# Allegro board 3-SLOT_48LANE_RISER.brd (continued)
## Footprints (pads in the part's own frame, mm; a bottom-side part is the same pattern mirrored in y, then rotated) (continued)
C0201
  rect 0.279x0.33 smd: 1(-0.229,0) 2(0.229,0)
C0201#2
  rect 0.305x0.381 smd: 1(-0.267,0) 2(0.267,0)
C0402
  rect 0.457x0.508 smd: 1(-0.4,0) 2(0.4,0)
C0603
  rect 0.813x0.711 smd: 1(-0.737,0) 2(0.737,0)
C0805
  rect 1.118x1.372 smd: 1(-0.95,0) 2(0.95,0)
C1206
  rect 1.168x1.575 smd: 1(-1.473,0) 2(1.473,0)
DELTAL_COUPON_7P
  round 0.66 smd: 1(-0.504,1.301) 2(0.497,1.301)
  round 1.143 hole 1.041: 3(-1.274,-2.498) 4(1.266,-2.498) 5(-1.274,3.852) 6(1.266,3.852)
  custom 0.743x0.743 smd: 7(-0.009,-0.37)
  round 0.508 hole 0.406: 8(-1.27,0.457) 9(-1.27,-0.762) 10(-0.025,-0.762) 11(1.27,-0.762) 12(1.27,0.457)
GF_PCIE_X16
  rect 0.762x3.2 smd: A1(-11.5,-3.42) B81(70.5,-3.42)
  rect 0.762x4.216 smd: A2(-10.5,-3.92) A3(-9.5,-3.92) A4(-8.5,-3.92) A5(-7.5,-3.92) A6(-6.5,-3.92) A7(-5.5,-3.92) A8(-4.5,-3.92) A9(-3.5,-3.92) A10(-2.5,-3.92) A11(-1.5,-3.92) A12(1.5,-3.92) A13(2.5,-3.92) A14(3.5,-3.92) A15(4.5,-3.92) A16(5.5,-3.92) A17(6.5,-3.92) A18(7.5,-3.92) A19(8.5,-3.92) A20(9.5,-3.92) A21(10.5,-3.92) A22(11.5,-3.92) A23(12.5,-3.92) A24(13.5,-3.92) A25(14.5,-3.92) A26(15.5,-3.92) A27(16.5,-3.92) A28(17.5,-3.92) A29(18.5,-3.92) A30(19.5,-3.92) A31(20.5,-3.92) A32(21.5,-3.92) A33(22.5,-3.92) A34(23.5,-3.92) A35(24.5,-3.92) A36(25.5,-3.92) A37(26.5,-3.92) A38(27.5,-3.92) A39(28.5,-3.92) A40(29.5,-3.92) A41(30.5,-3.92) A42(31.5,-3.92) A43(32.5,-3.92) A44(33.5,-3.92) A45(34.5,-3.92) A46(35.5,-3.92) A47(36.5,-3.92) A48(37.5,-3.92) A49(38.5,-3.92) A50(39.5,-3.92) A51(40.5,-3.92) A52(41.5,-3.92) A53(42.5,-3.92) A54(43.5,-3.92) A55(44.5,-3.92) A56(45.5,-3.92) A57(46.5,-3.92) A58(47.5,-3.92) A59(48.5,-3.92) A60(49.5,-3.92) A61(50.5,-3.92) A62(51.5,-3.92) A63(52.5,-3.92) A64(53.5,-3.92) A65(54.5,-3.92) A66(55.5,-3.92) A67(56.5,-3.92) A68(57.5,-3.92) A69(58.5,-3.92) A70(59.5,-3.92) A71(60.5,-3.92) A72(61.5,-3.92) A73(62.5,-3.92) A74(63.5,-3.92) A75(64.5,-3.92) A76(65.5,-3.92) A77(66.5,-3.92) A78(67.5,-3.92) A79(68.5,-3.92) A80(69.5,-3.92) A81(70.5,-3.92) A82(71.5,-3.92) B1(-11.5,-3.92) B2(-10.5,-3.92) B3(-9.5,-3.92) B4(-8.5,-3.92) B5(-7.5,-3.92) B6(-6.5,-3.92) B7(-5.5,-3.92) B8(-4.5,-3.92) B9(-3.5,-3.92) B10(-2.5,-3.92) B11(-1.5,-3.92) B12(1.5,-3.92) B13(2.5,-3.92) B14(3.5,-3.92) B15(4.5,-3.92) B16(5.5,-3.92) B17(6.5,-3.92) B18(7.5,-3.92) B19(8.5,-3.92) B20(9.5,-3.92) B21(10.5,-3.92) B22(11.5,-3.92) B23(12.5,-3.92) B24(13.5,-3.92) B25(14.5,-3.92) B26(15.5,-3.92) B27(16.5,-3.92) B28(17.5,-3.92) B29(18.5,-3.92) B30(19.5,-3.92) B31(20.5,-3.92) B32(21.5,-3.92) B33(22.5,-3.92) B34(23.5,-3.92) B35(24.5,-3.92) B36(25.5,-3.92) B37(26.5,-3.92) B38(27.5,-3.92) B39(28.5,-3.92) B40(29.5,-3.92) B41(30.5,-3.92) B42(31.5,-3.92) B43(32.5,-3.92) B44(33.5,-3.92) B45(34.5,-3.92) B46(35.5,-3.92) B47(36.5,-3.92) B48(37.5,-3.92) B49(38.5,-3.92) B50(39.5,-3.92) B51(40.5,-3.92) B52(41.5,-3.92) B53(42.5,-3.92) B54(43.5,-3.92) B55(44.5,-3.92) B56(45.5,-3.92) B57(46.5,-3.92) B58(47.5,-3.92) B59(48.5,-3.92) B60(49.5,-3.92) B61(50.5,-3.92) B62(51.5,-3.92) B63(52.5,-3.92) B64(53.5,-3.92) B65(54.5,-3.92) B66(55.5,-3.92) B67(56.5,-3.92) B68(57.5,-3.92) B69(58.5,-3.92) B70(59.5,-3.92) B71(60.5,-3.92) B72(61.5,-3.92) B73(62.5,-3.92) B74(63.5,-3.92) B75(64.5,-3.92) B76(65.5,-3.92) B77(66.5,-3.92) B78(67.5,-3.92) B79(68.5,-3.92) B80(69.5,-3.92) B82(71.5,-3.92)
GND_C10D4_6-5B10_OB5
  round 4.013 hole 4.013 unplated: (0,0)
  round 0.762 hole 0.559: 2(-3.5,0) 3(-2.475,2.475) 4(0,3.5) 5(2.475,2.475) 6(3.5,0)
HEADER1X4S2NH_P2H2_RA
  round 1.194 hole 1.194 unplated: (-2,-0.013) (2,-0.013)
  rect 1.041x2.032 smd: 1(-3,-3.188) 2(-1,-3.188) 3(1,-3.188) 4(3,-3.188)
HOLE_C10D5-6B10_NPB_H11_STANDOFF
  round 10.008 hole 5.613: 1(0,0)
HOLE_D3N_PKO10
  round 3.023 hole 3.023 unplated: (0,0)
IND_PCMB104T
  rect 4.115x4.115 smd: 1(-4.75,0) 2(4.75,0)
IND_PCMB104TXA
  rect 4.115x4.115 smd: 1(-4.75,0) 2(4.75,0)
IND_PCMC063T
  rect 2.362x3.505 smd: 1(-3.025,0) 2(3.025,0)
LED0603
  rect 0.813x0.813 smd: A(-0.75,0) C(0.75,0)
MSOP8_P0-65H1-1
  rect 1.6x0.305 smd: 1(-2,0.975) 2(-2,0.325) 3(-2,-0.325) 4(-2,-0.975) 5(2,-0.975) 6(2,-0.325) 7(2,0.325) 8(2,0.975)
MSOP10_P0-5W4-4_3X3
  rect 1.422x0.279 smd: 1(-2.2,1) 2(-2.2,0.5) 3(-2.2,0) 4(-2.2,-0.5) 5(-2.2,-1) 6(2.2,-1) 7(2.2,-0.5) 8(2.2,0) 9(2.2,0.5) 10(2.2,1)
PCIE_X16D_H11
  round 2.413 hole 2.413 unplated: (-1.25,-11.65) (-1.25,-84.8)
  rect 1.194x1.194 hole 0.711: A1(0,0)
  round 1.194 hole 0.711: A2(2,-1) A3(0,-2) A4(2,-3) A5(0,-4) A6(2,-5) A7(0,-6) A8(2,-7) A9(0,-8) A10(2,-9) A11(0,-10) A12(2,-13) A13(0,-14) A14(2,-15) A15(0,-16) A16(2,-17) A17(0,-18) A18(2,-19) A19(0,-20) A20(2,-21) A21(0,-22) A22(2,-23) A23(0,-24) A24(2,-25) A25(0,-26) A26(2,-27) A27(0,-28) A28(2,-29) A29(0,-30) A30(2,-31) A31(0,-32) A32(2,-33) A33(0,-34) A34(2,-35) A35(0,-36) A36(2,-37) A37(0,-38) A38(2,-39) A39(0,-40) A40(2,-41) A41(0,-42) A42(2,-43) A43(0,-44) A44(2,-45) A45(0,-46) A46(2,-47) A47(0,-48) A48(2,-49) A49(0,-50) A50(2,-51) A51(0,-52) A52(2,-53) A53(0,-54) A54(2,-55) A55(0,-56) A56(2,-57) A57(0,-58) A58(2,-59) A59(0,-60) A60(2,-61) A61(0,-62) A62(2,-63) A63(0,-64) A64(2,-65) A65(0,-66) A66(2,-67) A67(0,-68) A68(2,-69) A69(0,-70) A70(2,-71) A71(0,-72) A72(2,-73) A73(0,-74) A74(2,-75) A75(0,-76) A76(2,-77) A77(0,-78) A78(2,-79) A79(0,-80) A80(2,-81) A81(0,-82) A82(2,-83) B1(-2.5,0) B2(-4.5,-1) B3(-2.5,-2) B4(-4.5,-3) B5(-2.5,-4) B6(-4.5,-5) B7(-2.5,-6) B8(-4.5,-7) B9(-2.5,-8) B10(-4.5,-9) B11(-2.5,-10) B12(-4.5,-13) B13(-2.5,-14) B14(-4.5,-15) B15(-2.5,-16) B16(-4.5,-17) B17(-2.5,-18) B18(-4.5,-19) B19(-2.5,-20) B20(-4.5,-21) B21(-2.5,-22) B22(-4.5,-23) B23(-2.5,-24) B24(-4.5,-25) B25(-2.5,-26) B26(-4.5,-27) B27(-2.5,-28) B28(-4.5,-29) B29(-2.5,-30) B30(-4.5,-31) B31(-2.5,-32) B32(-4.5,-33) B33(-2.5,-34) B34(-4.5,-35) B35(-2.5,-36) B36(-4.5,-37) B37(-2.5,-38) B38(-4.5,-39) B39(-2.5,-40) B40(-4.5,-41) B41(-2.5,-42) B42(-4.5,-43) B43(-2.5,-44) B44(-4.5,-45) B45(-2.5,-46) B46(-4.5,-47) B47(-2.5,-48) B48(-4.5,-49) B49(-2.5,-50) B50(-4.5,-51) B51(-2.5,-52) B52(-4.5,-53) B53(-2.5,-54) B54(-4.5,-55) B55(-2.5,-56) B56(-4.5,-57) B57(-2.5,-58) B58(-4.5,-59) B59(-2.5,-60) B60(-4.5,-61) B61(-2.5,-62) B62(-4.5,-63) B63(-2.5,-64) B64(-4.5,-65) B65(-2.5,-66) B66(-4.5,-67) B67(-2.5,-68) B68(-4.5,-69) B69(-2.5,-70) B70(-4.5,-71) B71(-2.5,-72) B72(-4.5,-73) B73(-2.5,-74) B74(-4.5,-75) B75(-2.5,-76) B76(-4.5,-77) B77(-2.5,-78) B78(-4.5,-79) B79(-2.5,-80) B80(-4.5,-81) B81(-2.5,-82) B82(-4.5,-83)
PQFN16_IR3823
  rect 0.305x0.66 smd: 1(-1.25,-1.78) 2(-0.75,-1.78) 3(-0.25,-1.78) 4(0.25,-1.78) 5(0.75,-1.78) 6(1.25,-1.78)
  rect 0.66x0.305 smd: 7(1.7,-1.03) 8(1.7,-0.53) 9(1.7,-0.03) 13(-1.7,-0.03) 14(-1.7,-0.53) 15(-1.7,-1.03)
  rect 0.787x1.067 smd: 10(1.69,0.92)
  rect 1.524x1.626 smd: 11(0.195,1.2)
  rect 1.321x1.626 smd: 12(-1.44,1.2)
  rect 2.438x1.422 smd: 16(0,-0.53)
PQFN17_IR3895
  rect 0.305x0.711 smd: 1(-1.95,-3) 2(-1.3,-3) 3(-0.65,-3) 4(0,-3) 5(0.65,-3) 6(1.3,-3) 7(1.95,-3)
  rect 0.711x0.305 smd: 8(2.45,-2.17) 9(2.45,-1.52) 10(2.45,-0.87) 14(-2.45,-0.87) 15(-2.45,-1.52) 16(-2.45,-2.17)
  custom 0.263x0.263 smd: 11(2.5,1.31)
  custom 0.533x0.533 smd: 12(0.28,2.91)
  custom 0.405x0.405 smd: 13(-2.5,1.31)
  rect 2.692x1.549 smd: 17(0,-1.51)
PQFN17_IR3899
  rect 0.254x0.762 smd: 1(-1.5,-2.425) 2(-1,-2.425) 3(-0.5,-2.425) 4(0,-2.425) 5(0.5,-2.425) 6(1,-2.425) 7(1.5,-2.425)
  rect 0.762x0.254 smd: 8(1.925,-1.645) 9(1.925,-1.145) 10(1.925,-0.645) 14(-1.925,-0.645) 15(-1.925,-1.145) 16(-1.925,-1.645)
  custom 0.2x0.2 smd: 11(1.695,1.205)
  custom 0.405x0.405 smd: 12(0.285,1.395)
  custom 0.343x0.343 smd: 13(-1.615,1.205)
  rect 2.184x1.194 smd: 17(0,-1.145)
PWR2X6D2NH_P3W3H8-9_RA
  round 3.023 hole 3.023 unplated: (-12.85,-4.32) (-2.15,-4.32)
  rect 1.549x1.549 hole 1.041: 1(0,0)
  round 1.549 hole 1.041: 2(-3,0) 3(-6,0) 4(-9,0) 5(-12,0) 6(-15,0) 7(0,3) 8(-3,3) 9(-6,3) 10(-9,3) 11(-12,3) 12(-15,3)
R0402
  rect 0.457x0.508 smd: 1(-0.4,0) 2(0.4,0)
R0603
  rect 0.813x0.711 smd: 1(-0.737,0) 2(0.737,0)
SC70-5XB
  rect 0.914x0.406 smd: 1(-1.1,0.65) 2(-1.1,0) 3(-1.1,-0.65) 4(1.1,-0.65) 5(1.1,0.65)
SLIVER_X8_RA
  round 1.118 hole 1.118 unplated: (-8.425,0.965) (8.375,2.965)
  rect 0.356x1.422 smd: 1(-7.225,5.115) 2(-6.625,5.115) 3(-6.025,5.115) 4(-5.425,5.115) 5(-4.825,5.115) 6(-4.225,5.115) 7(-3.625,5.115) 8(-3.025,5.115) 9(-2.425,5.115) 10(-1.825,5.115) 11(-1.225,5.115) 12(-0.625,5.115) 13(-0.025,5.115) 14(0.575,5.115) 15(1.175,5.115) 16(1.775,5.115) 17(2.375,5.115) 18(2.975,5.115) 19(3.575,5.115) 20(4.175,5.115) 21(4.775,5.115) 22(5.375,5.115) 23(5.975,5.115) 24(6.575,5.115) 25(7.175,5.115) 26(7.175,8.065) 27(6.575,8.065) 28(5.975,8.065) 29(5.375,8.065) 30(4.775,8.065) 31(4.175,8.065) 32(3.575,8.065) 33(2.975,8.065) 34(2.375,8.065) 35(1.775,8.065) 36(1.175,8.065) 37(0.575,8.065) 38(-0.025,8.065) 39(-0.625,8.065) 40(-1.225,8.065) 41(-1.825,8.065) 42(-2.425,8.065) 43(-3.025,8.065) 44(-3.625,8.065) 45(-4.225,8.065) 46(-4.825,8.065) 47(-5.425,8.065) 48(-6.025,8.065) 49(-6.625,8.065) 50(-7.225,8.065)
  round 1.626 hole 1.118: G1(-9.775,4.565) G4(9.725,-0.585)
  round 1.016 hole 0.61: G2(-9.775,1.411) G3(9.725,2.565)
SOIC8
  rect 1.727x0.559 smd: 1(-2.642,1.905) 2(-2.642,0.635) 3(-2.642,-0.635) 4(-2.642,-1.905) 5(2.642,-1.905) 6(2.642,-0.635) 7(2.642,0.635) 8(2.642,1.905)
SOT23
  rect 0.914x0.813 smd: 1(-1,0.95) 2(-1,-0.95) 3(1,0)
SOT23_GDS
  rect 1.422x1.016 smd: D(1.1,0) G(-1.1,0.95) S(-1.1,-0.95)
TAJ_D_7-3X4-3
  rect 2.388x2.438 smd: 1(-3.12,0) 2(3.12,0)
TSSOP8_D65_1D2
  rect 1.168x0.61 smd: 1(-2.175,1.05) 4(-2.175,-1.05) 5(2.175,-1.05) 8(2.175,1.05)
  rect 1.168x0.432 smd: 2(-2.175,0.325) 3(-2.175,-0.325) 6(2.175,-0.325) 7(2.175,0.325)
TSSOP24_P0-65W5-6H1-2
  rect 1.6x0.305 smd: 1(-2.8,3.575) 2(-2.8,2.925) 3(-2.8,2.275) 4(-2.8,1.625) 5(-2.8,0.975) 6(-2.8,0.325) 7(-2.8,-0.325) 8(-2.8,-0.975) 9(-2.8,-1.625) 10(-2.8,-2.275) 11(-2.8,-2.925) 12(-2.8,-3.575) 13(2.8,-3.575) 14(2.8,-2.925) 15(2.8,-2.275) 16(2.8,-1.625) 17(2.8,-0.975) 18(2.8,-0.325) 19(2.8,0.325) 20(2.8,0.975) 21(2.8,1.625) 22(2.8,2.275) 23(2.8,2.925) 24(2.8,3.575)
unnamed#2
  round 0.991 smd: 1(0,0)
VFQFPN40_P0-4_EPAD
  custom 0.044x0.044 smd: 1(-2.45,1.8) 2(-2.45,1.4) 3(-2.45,1) 4(-2.45,0.6) 5(-2.45,0.2) 6(-2.45,-0.2) 7(-2.45,-0.6) 8(-2.45,-1) 9(-2.45,-1.4) 10(-2.45,-1.8) 11(-1.8,-2.45) 12(-1.4,-2.45) 13(-1,-2.45) 14(-0.6,-2.45) 15(-0.2,-2.45) 16(0.2,-2.45) 17(0.6,-2.45) 18(1,-2.45) 19(1.4,-2.45) 20(1.8,-2.45) 21(2.45,-1.8) 22(2.45,-1.4) 23(2.45,-1) 24(2.45,-0.6) 25(2.45,-0.2) 26(2.45,0.2) 27(2.45,0.6) 28(2.45,1) 29(2.45,1.4) 30(2.45,1.8) 31(1.8,2.45) 32(1.4,2.45) 33(1,2.45) 34(0.6,2.45) 35(0.2,2.45) 36(-0.2,2.45) 37(-0.6,2.45) 38(-1,2.45) 39(-1.4,2.45) 40(-1.8,2.45)
  rect 3.607x3.607 smd: 41(0,0)
X2QFN10_0-5_2X1-5
  rect 0.584x0.305 smd: 1(-0.638,0.75) 4(-0.638,-0.75) 6(0.638,-0.75) 9(0.638,0.75)
  rect 0.584x0.254 smd: 2(-0.638,0.25) 3(-0.638,-0.25) 7(0.638,-0.25) 8(0.638,0.25)
  rect 0.279x0.635 smd: 5(0,-0.86) 10(0,0.86)

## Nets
GND: C1.2(B) C2.2(B) C3.2(B) C4.2(B) C5.2(B) C6.2(B) C7.2(B) C8.2(B) C9.2(B) C10.2(B) C11.2(B) C12.2(B) C13.2(B) C14.2(B) C15.2(B) C16.2(B) C17.2(B) C18.2(B) C19.2(B) C20.2(B) C21.2(B) C22.2(B) C47.2(B) C48.2(B) C49.2(B) C50.2(B) C51.2(B) C52.2(B) C53.2(B) C54.2(B) C127.2(B) C128.2(B) C129.2(B) C130.2(B) C131.2(B) C132.2(B) C133.2(B) C134.2(B) C135.2(B) C136.2(B) C137.2(B) C138.2(B) C139.2(B) C140.2(B) C141.2(B) C142.2(B) C143.2(B) C144.2(B) C145.2(B) C146.2(B) C147.2(B) C148.2(B) C149.2(B) C150.2(B) C151.2(B) C152.2(B) C153.2(B) C154.2(B) C155.2(B) C156.2(B) C157.2(B) C158.2(B) C159.2(B) C160.2(B) C161.2(B) C162.2(B) C163.2(B) C164.2(B) C165.2(B) C166.2(B) C167.2(B) C168.2(B) C169.2(B) C170.2(B) C171.2(B) C172.2(B) C173.2(B) C174.2(B) C175.2(B) C176.2(B) C177.2(B) C178.2(B) C179.2(B) C180.2(B) C181.2(B) C182.2(B) C183.2(B) C184.2(B) C185.2(B) C186.2(B) C187.2(B) C188.2(B) C189.2(B) C190.2(B) C191.2(B) C192.2(B) C193.2(B) C194.2(B) C215.2(B) C216.2(B) C217.2(B) C218.2(B) C219.2(B) C220.2(B) C221.2(B) C222.2(B) C223.2(B) C224.2(B) C225.2(B) C226.2(B) C227.2(B) C242.2(B) C243.2(B) C244.2(B) C245.2(B) C246.2(B) C247.2(B) C248.2(B) C249.2(B) C250.2(B) C251.2(B) C252.2(B) C253.2(B) C254.2(B) C255.2(B) C257.2(B) C258.2(B) C259.2(B) C265.2(B) C269.2(B) C271.2(B) C273.2(B) C275.2(B) C277.2(B) C279.2(B) C281.2(B) C283.2(B) C287.2(B) C290.2(B) C294.2(B) C297.2(B) C352.2(B) C386.2(B) C390.2(B) C394.2(B) C398.2(B) C402.2(B) C406.2(B) C410.2(B) C414.2(B) C418.2(B) C422.2(B) C426.2(B) C430.2(B) C434.2(B) C438.2(B) C442.2(B) C450.2(B) C451.2(B) C452.2(B) C455.2(B) C456.2(B) C460.2(B) C461.2(B) C463.2(B) C464.2(B) C465.2(B) C466.2(B) C467.2(B) C477.2(B) C478.2(B) C479.2(B) C480.2(B) CON1.4 H1.1 J1.A4 J1.A12 J1.A15 J1.A18 J1.A20 J1.A23 J1.A24 J1.A27 J1.A28 J1.A31 J1.A34 J1.A37 J1.A38 J1.A41 J1.A42 J1.A45 J1.A46 J1.A49 J1.A51 J1.A54 J1.A55 J1.A58 J1.A59 J1.A62 J1.A63 J1.A66 J1.A67 J1.A70 J1.A71 J1.A74 J1.A75 J1.A78 J1.A79 J1.A82 J1.B4 J1.B7 J1.B13 J1.B16 J1.B18 J1.B21 J1.B22 J1.B25 J1.B26 J1.B29 J1.B32 J1.B35 J1.B36 J1.B39 J1.B40 J1.B43 J1.B44 J1.B47 J1.B49 J1.B52 J1.B53 J1.B56 J1.B57 J1.B60 J1.B61 J1.B64 J1.B65 J1.B68 J1.B69 J1.B72 J1.B73 J1.B76 J1.B77 J1.B80 J2.A4 J2.A12 J2.A15 J2.A18 J2.A20 J2.A23 J2.A24 J2.A27 J2.A28 J2.A31 J2.A34 J2.A37 J2.A38 J2.A41 J2.A42 J2.A45 J2.A46 J2.A49 J2.A51 J2.A54 J2.A55 J2.A58 J2.A59 J2.A62 J2.A63 J2.A66 J2.A67 J2.A70 J2.A71 J2.A74 J2.A75 J2.A78 J2.A79 J2.A82 J2.B4 J2.B7 J2.B13 J2.B16 J2.B18 J2.B21 J2.B22 J2.B25 J2.B26 J2.B29 J2.B32 J2.B35 J2.B36 J2.B39 J2.B40 J2.B43 J2.B44 J2.B47 J2.B49 J2.B52 J2.B53 J2.B56 J2.B57 J2.B60 J2.B61 J2.B64 J2.B65 J2.B68 J2.B69 J2.B72 J2.B73 J2.B76 J2.B77 J2.B80 J3.A4 J3.A12 J3.A15 J3.A18 J3.A20 J3.A23 J3.A24 J3.A27 J3.A28 J3.A31 J3.A34 J3.A37 J3.A38 J3.A41 J3.A42 J3.A45 J3.A46 J3.A49 J3.A51 J3.A54 J3.A55 J3.A58 J3.A59 J3.A62 J3.A63 J3.A66 J3.A67 J3.A70 J3.A71 J3.A74 J3.A75 J3.A78 J3.A79 J3.A82 J3.B4 J3.B7 J3.B13 J3.B16 J3.B18 J3.B21 J3.B22 J3.B25 J3.B26 J3.B29 J3.B32 J3.B35 J3.B36 J3.B39 J3.B40 J3.B43 J3.B44 J3.B47 J3.B49 J3.B52 J3.B53 J3.B56 J3.B57 J3.B60 J3.B61 J3.B64 J3.B65 J3.B68 J3.B69 J3.B72 J3.B73 J3.B76 J3.B77 J3.B80 J5.A4 J5.A12 J5.A15 J5.A18 J5.A20 J5.A23 J5.A24 J5.A27 J5.A28 J5.A31 J5.A34 J5.A37 J5.A38 J5.A41 J5.A42 J5.A45 J5.A46 J5.A49 J5.A51 J5.A54 J5.A55 J5.A58 J5.A59 J5.A62 J5.A63 J5.A66 J5.A67 J5.A70 J5.A71 J5.A74 J5.A75 J5.A78 J5.A79 J5.A82 J5.B4 J5.B7 J5.B13 J5.B16 J5.B18 J5.B21 J5.B22 J5.B25 J5.B26 J5.B29 J5.B32 J5.B35 J5.B36 J5.B39 J5.B40 J5.B43 J5.B44 J5.B47 J5.B49 J5.B52 J5.B53 J5.B56 J5.B57 J5.B60 J5.B61 J5.B64 J5.B65 J5.B68 J5.B69 J5.B72 J5.B73 J5.B76 J5.B77 J5.B80 J6.7 J6.8 J6.9 J6.10 J6.11 J6.12 J7.1 J7.4 J7.7 J7.10 J7.13 J7.16 J7.19 J7.22 J7.25 J7.26 J7.29 J7.32 J7.35 J7.38 J7.41 J7.44 J7.47 J7.50 J7.G1 J7.G2 J7.G3 J7.G4 J8.1 J8.4 J8.7 J8.10 J8.13 J8.16 J8.19 J8.22 J8.25 J8.26 J8.29 J8.32 J8.35 J8.38 J8.41 J8.44 J8.47 J8.50 J8.G1 J8.G2 J8.G3 J8.G4 MH5.2 MH5.3 MH5.4 MH5.5 MH5.6 MH6.2 MH6.3 MH6.4 MH6.5 MH6.6 MH7.2 MH7.3 MH7.4 MH7.5 MH7.6 MH8.1 MH9.2 MH9.3 MH9.4 MH9.5 MH9.6 MH10.2 MH10.3 MH10.4 MH10.5 MH10.6 MH11.2 MH11.3 MH11.4 MH11.5 MH11.6 PC506.2(B) PC508.1 PC510.2(B) PC511.2(B) PC515.2(B) PC517.2(B) PC519.2(B) PC520.2(B) PC521.2(B) PC522.2(B) PC524.2(B) PC526.2(B) PC529.2(B) PC530.2(B) PC531.2(B) PC532.2(B) PC533.2(B) PC539.2(B) PC541.2(B) PC542.2(B) PC543.2(B) PC545.2(B) PC548.2(B) PC550.2(B) PC551.2(B) PC552.2(B) PC553.2(B) PC554.2(B) PC556.2(B) PC557.2(B) PC580.2(B) PC581.1 PC583.2(B) PC584.2(B) PC585.2(B) PC586.2(B) PC588.2(B) PC592.2(B) PC593.2(B) PC594.2(B) PC595.2(B) PC596.2(B) PC598.2(B) PC599.2(B) PC600.2(B) PC788.2(B) PC1531.2(B) PC1533.2(B) PC1588.2(B) PC1589.2(B) PC1592.2(B) PC1594.2(B) PC1595.2(B) PC1596.2(B) PC1598.2(B) PC1599.2(B) PC1600.2(B) PC2596.2(B) PR333.2(B) PR340.2(B) PR361.2(B) PR369.2(B) PR424.2(B) PR435.2(B) PR505.2(B) PU17.11 PU19.10 PU23.11 Q1.S Q2.S Q3.S Q4.S Q7.S R2.2(B) R10.2(B) R11.2(B) R12.2(B) R13.2(B) R14.2(B) R15.2(B) R16.2(B) R17.2(B) R18.2(B) R19.2(B) R20.2(B) R23.2(B) R24.2(B) R31.2(B) R32.2(B) R33.2(B) R35.2(B) R36.2(B) R37.2(B) R38.2(B) R41.2(B) R42.2(B) R43.2(B) R58.2(B) R59.2(B) R61.2(B) R63.2(B) R65.2(B) R66.2(B) R67.2(B) R68.2(B) R71.2(B) R73.2(B) R75.2(B) R76.1 R80.2(B) R82.2(B) R84.2(B) R108.2(B) R112.2(B) R114.2(B) R116.2(B) R132.2(B) R133.2(B) R134.2(B) R135.2(B) R199.2(B) R200.2(B) R260.1 R275.1 R282.2(B) R284.2(B) R286.2(B) R294.2(B) R310.2(B) R318.2(B) R358.1 U1.A3 U1.A6 U1.A9 U1.A12 U1.A15 U1.A18 U1.A21 U1.AA3 U1.AA6 U1.AA9 U1.AA12 U1.AA15 U1.AB3 U1.AB6 U1.AB9 U1.AB12 U1.AB15 U1.AB18 U1.AB21 U1.AC1 U1.AC2 U1.AC3 U1.AC4 U1.AC5 U1.AC6 U1.AC7 U1.AC8 U1.AC9 U1.AC10 U1.AC11 U1.AC12 U1.AC13 U1.AC14 U1.AC15 U1.AC16 U1.AC17 U1.AC18 U1.AC19 U1.AC20 U1.AC21 U1.AC22 U1.AC23 U1.AD15 U1.AE3 U1.AE6 U1.AE9 U1.AE12 U1.AE15 U1.AE18 U1.AE21 U1.C1 U1.C2 U1.C3 U1.C4 U1.C5 U1.C6 U1.C7 U1.C8 U1.C9 U1.C10 U1.C11 U1.C12 U1.C13 U1.C14 U1.C15 U1.C16 U1.C17 U1.C18 U1.C19 U1.C20 U1.C21 U1.C22 U1.C23 U1.D3 U1.D6 U1.D9 U1.D12 U1.D15 U1.D18 U1.D21 U1.E3 U1.E6 U1.E9 U1.E12 U1.E15 U1.E18 U1.E21 U1.F6 U1.F9 U1.F12 U1.F15 U1.F18 U1.G1 U1.G2 U1.G3 U1.G4 U1.G5 U1.G6 U1.G9 U1.G12 U1.G15 U1.G18 U1.G19 U1.G20 U1.G21 U1.G22 U1.G23 U1.H3 U1.H21 U1.J3 U1.J21 U1.K1 U1.K4 U1.K5 U1.K9 U1.K11 U1.K13 U1.K15 U1.K20 U1.K21 U1.K23 U1.L3 U1.L8 U1.L10 U1.L12 U1.L14 U1.L16 U1.L21 U1.M3 U1.M9 U1.M11 U1.M13 U1.M15 U1.M21 U1.N1 U1.N4 U1.N5 U1.N8 U1.N10 U1.N12 U1.N14 U1.N16 U1.N20 U1.N21 U1.N23 U1.P3 U1.P9 U1.P11 U1.P13 U1.P15 U1.P21 U1.R3 U1.R8 U1.R10 U1.R12 U1.R14 U1.R16 U1.R21 U1.T1 U1.T4 U1.T5 U1.T9 U1.T11 U1.T13 U1.T15 U1.T20 U1.T23 U1.U3 U1.U21 U1.V3 U1.V6 U1.V9 U1.V21 U1.W1 U1.W4 U1.W9 U1.W12 U1.W17 U1.W18 U1.W19 U1.W20 U1.W21 U1.W22 U1.W23 U1.Y1 U1.Y7 U1.Y8 U1.Y9(VSS_Y9) U1.Y12 U1.Y15 U1.Y18 U1.Y21 U1.Y23 U2.12 U3.3 U4.5 U6.4 U7.4 U8.3 U9.4 U9.41 U10.6 U11.3 U12.4 U13.3 U16.3 U17.3 U19.3 U20.3 U47.3
GND_L: U5.3 U5.4 U5.5 U5.6 U5.7 U5.8 U5.9 U5.10 U5.11 U5.12 U25.3 U25.4 U25.5 U25.6 U25.7 U25.8 U25.9 U25.10 U25.11 U25.12 U26.3 U26.4 U26.5 U26.6 U26.7 U26.8 U26.9 U26.10 U26.11 U26.12 U29.3 U29.4 U29.5 U29.6 U29.7 U29.8 U29.9 U29.10 U29.11 U29.12 U30.3 U30.4 U30.5 U30.6 U30.7 U30.8 U30.9 U30.10 U30.11 U30.12 U33.3 U33.4 U33.5 U33.6 U33.7 U33.8 U33.9 U33.10 U33.11 U33.12 U34.3 U34.4 U34.5 U34.6 U34.7 U34.8 U34.9 U34.10 U34.11 U34.12 U37.3 U37.4 U37.5 U37.6 U37.7 U37.8 U37.9 U37.10 U37.11 U37.12 U39.3 U39.4 U39.5 U39.6 U39.7 U39.8 U39.9 U39.10 U39.11 U39.12 U41.3 U41.4 U41.5 U41.6 U41.7 U41.8 U41.9 U41.10 U41.11 U41.12 U43.3 U43.4 U43.5 U43.6 U43.7 U43.8 U43.9 U43.10 U43.11 U43.12 U45.3 U45.4 U45.5 U45.6 U45.7 U45.8 U45.9 U45.10 U45.11 U45.12
P0V9: C9.1 C16.1 C18.1 C20.1 C22.1 C145.1 C147.1 C165.1 C170.1 C173.1 C174.1 C176.1 C269.1 C271.1 C273.1 C275.1 C277.1 C279.1 C281.1 C283.1 C287.1 C290.1 C294.1 C297.1 C386.1 C394.1 C398.1 C402.1 C410.1 C414.1 C418.1 C422.1 C426.1 C430.1 C434.1 C438.1 C442.1 L3.1 L4.1 L5.1 L6.1 PC592.1 PC594.1 PC595.1 PC596.1 PC598.1 PC599.1 PC600.1 PC1592.1 PC1594.1 PC1595.1 PC1596.1 PC1598.1 PC1599.1 PC1600.1 PC2596.1 PL11.2 PR430.2(B) PR433.2(B) PR434.2(B) R148.1 U1.K8 U1.K10 U1.K12 U1.K14 U1.K16 U1.L9 U1.L11 U1.L13 U1.L15 U1.M8 U1.M10 U1.M12 U1.M14 U1.M16 U1.N9 U1.N11 U1.N13 U1.N15 U1.P8 U1.P10 U1.P12 U1.P14 U1.P16 U1.R9 U1.R11 U1.R13 U1.R15 U1.T8 U1.T10 U1.T12 U1.T14 U1.T16
P0V9_A: C2.1 C3.1 C4.1 C5.1 C6.1 C7.1 C8.1 C10.1 C11.1 C12.1 C13.1 C14.1 C15.1 C17.1 C19.1 C21.1 C141.1 C142.1 C143.1 C144.1 C146.1 C148.1 C149.1 C150.1 C151.1 C160.1 C161.1 C162.1 C163.1 C164.1 C166.1 C167.1 C171.1 C175.1 C177.1 C182.1 C183.1 C184.1 C185.1 C186.1 C187.1 C188.1 C194.1 C390.1 C406.1 L3.2 L4.2 L5.2 L6.2 U1.H6 U1.H7 U1.H8 U1.H9 U1.H12 U1.H15 U1.H16 U1.H17 U1.J7 U1.J8 U1.J9 U1.J11 U1.J13 U1.J15 U1.J16 U1.J18 U1.K6 U1.K17 U1.K18 U1.L18 U1.M7 U1.M17 U1.N7 U1.N17 U1.R6 U1.R7 U1.T6 U1.T18 U1.U8 U1.U9 U1.U11 U1.U14 U1.U15 U1.U16 U1.U17 U1.U18 U1.V12 U1.V15 U1.V16
P0V9_AGND: PC582.2(B) PR423.2(B) PR424.1 PR504.1 PU23.4 PU23.17
P0V9_COMP: PC589.1 PR427.1 PU23.3
P0V9_COMP_RC: PC591.1 PR427.2(B)
P0V9_EN: PC580.1 PR418.2(B) PU23.15
P0V9_FB: PC589.2(B) PC591.2(B) PR429.2(B) PR431.1 PR432.1 PU23.1
P0V9_FB_RC: PC597.1 PR431.2(B)
P0V9_PG: PR420.2(B) PU23.7 Q7.G R297.1
P0V9_PG_LED_H: D1.A R110.1
P0V9_PG_LED_N: D1.C Q7.D R109.2(B)
P0V9_RT: PR423.1 PU23.5
P0V9_SENSE_R_N: PR428.1 PR429.1 PR435.1 PR504.2(B) PR505.1
P0V9_SENSE_R_P: PC597.2(B) PR432.2(B) PR433.1 PR434.1
P0V9_VCC: PC581.2(B) PU23.6 PU23.10
P0V9_VIN: PC583.1 PR426.2(B) PU23.9
P0V9_VREF: PC582.1 PU23.2
P0V9_VSNS: PR428.2(B) PR430.1 PU23.8(VSNS)
P1V8: C1.1 C48.1 C50.1 C52.1 C53.1 C127.1 C129.1 C131.1 C133.1 C135.1 C137.1 C139.1 C181.1 C191.1 C451.1 L2.2 PC551.1 PC552.1 PC554.1 PC556.1 PC557.1 PL8.2 PR375.2(B) R46.1 R47.1 R48.1 R49.1 R50.1 R51.1 R52.1 R53.1 R54.1 R55.1 R56.1 R57.1 R60.1 R62.1 R64.1 R69.1 R70.1 R72.1 R74.1 R93.1 R94.1 R111.1 R113.1 R115.1 R117.1 R120.1 R121.1 R128.1 R129.1 R146.1 R277.1 R278.1 R351.1 U1.J12 U1.J17 U1.K7 U1.N6 U1.N18 U1.T7 U1.T17 U1.U12 U6.8 U12.1 U13.5
P1V8_A: C47.1 C49.1 C51.1 C54.1 C128.1 C130.1 C132.1 C134.1 C136.1 C138.1 C140.1 L2.1 U1.J10 U1.J14 U1.L7 U1.L17 U1.R17 U1.U7 U1.U10 U1.U13
P1V8_AGND: PR367.2(B) PR368.2(B) PR369.1 PR372.1 PU19.4 PU19.9 PU19.13 PU19.16
P1V8_COMP: PC547.1 PR371.1 PU19.3
P1V8_COMP_RC: PC549.1 PR371.2(B)
P1V8_EN: PC539.1 PR357.2(B) PR361.1 PU19.15
P1V8_FB: PC547.2(B) PC549.2(B) PR372.2(B) PR373.1 PR374.1 PU19.1
P1V8_FB_RC: PC555.1 PR373.2(B)
P1V8_PG: PR363.2(B) PR418.1 PU19.6 R276.2(B)
P1V8_RT: PR368.1 PU19.5
P1V8_SS: PR366.2(B) PR367.1 PU19.2
P1V8_VCC: PC541.1 PR366.1 PU19.8
P1V8_VIN: PC542.1 PR370.2(B) PU19.7
P1V8_VSENSE_R: PC555.2(B) PR374.2(B) PR375.1
P3V3: C155.1 C156.1 C157.1 C172.1 C245.1 C246.1 C247.1 C450.1 C455.1 C456.1 C478.1 C480.1 CON1.1 J2.A9 J2.A10 J2.B8 J3.A9 J3.A10 J3.B8 L1.2 PC522.1 PC524.1 PC526.1 PC529.1 PC530.1 PC531.1 PC533.1 PC1531.1 PC1533.1 PL6.2 PR336.1 PR345.2(B) PR348.2(B) PR363.1 PR420.1 R3.1 R4.1 R6.1 R107.1 R109.1 R110.2(B) R137.1 R147.1 R153.1 R154.1 R155.1 R156.1 R159.1 R160.1 R161.1 R162.1 R163.1 R164.1 R191.1 R192.1 R193.1 R194.1 R203.1 R204.1 R209.1 R210.1 R296.1 R301.1 R303.1 R304.1 R317.1 R342.1 R348.1 R352.1 R353.1 U11.5 U12.8(VCCB) U16.5 U17.5
P3V3_AGND: PC509.2(B) PR339.2(B) PR340.1 PR343.1 PR344.1 PU17.4 PU17.17
P3V3_BUF_VDDA: C224.1 C225.1 R92.2(B) U9.1
P3V3_BUF_VDDR: C226.1 C227.1 R91.2(B) U9.5
P3V3_CLK_BUF_VDD: C215.1 C216.1 C217.1 C218.1 C219.1 C220.1 C221.1 C222.1 C257.1 C258.1 L1.1 R1.1 R91.1 R92.1 U9.12 U9.16 U9.20 U9.21 U9.25 U9.29 U9.31 U9.35 U9.39
P3V3_COMP: PC516.1 PR342.1 PU17.3
P3V3_COMP_RC: PC518.1 PR342.2(B)
P3V3_EN: PC506.1 PR332.2(B) PR333.1 PU17.15
P3V3_FB: PC516.2(B) PC518.2(B) PR344.2(B) PR346.1 PR347.1 PU17.1
P3V3_FB_RC: PC527.1 PR346.2(B)
P3V3_MB: C169.1 C252.1 C253.1 C254.1 J1.A9 J1.A10 J1.B8 J5.A9 J5.A10 J5.B8 R360.1
P3V3_PG: PR336.2(B) PR357.1 PU17.7 R298.1
P3V3_RT: PR339.1 PU17.5
P3V3_SENSE_R: PC527.2(B) PR347.2(B) PR348.1
P3V3_STBY_MB: C158.1 C159.1 C178.1 C179.1 C223.1 C248.1 C255.1 C259.1 C265.1 C352.1 C452.1 C460.1 C461.1 J1.B10 J2.B10 J3.B10 J5.B10 R78.1 R79.1 R81.1 R83.1 R87.1 R88.1 R95.1 R96.1 R97.1 R98.1 R99.1 R100.1 R101.1 R102.1 R103.1 R104.1 R105.1 R106.1 R144.1 R145.1 R150.1 R151.1 R185.1 R186.1 R252.1 R257.1 R258.1 R259.1 R261.1 R262.1 R263.1 R264.1 R281.1 R283.1 R285.1 R293.1 R302.1 R309.1 R341.1 R356.1 R357.1 R359.1 U2.24 U3.8(VDD) U4.1(VDD) U7.8 U8.5 U10.1(VDD) U19.5 U20.5 U47.5
P3V3_VCC: PC508.2(B) PU17.6 PU17.10
P3V3_VIN: PC510.1 PR341.2(B) PU17.9
P3V3_VREF: PC509.1 PU17.2
P3V3_VSNS: PR343.2(B) PR345.1 PU17.8(VSNS)
P12V: C152.1 C153.1 C154.1 C242.1 C243.1 C244.1 C463.1 C464.1 C465.1 C477.1 C479.1 J2.A2 J2.A3 J2.B1 J2.B2 J2.B3 J3.A2 J3.A3 J3.B1 J3.B2 J3.B3 J6.1 J6.2 J6.3 J6.4 J6.5 PC532.1 PC553.1 PC593.1 PL9.2 PL12.2 PL20.2 PR332.1
P12V_MB: C168.1 C249.1 C250.1 C251.1 J1.A2 J1.A3 J1.B1 J1.B2 J1.B3 J5.A2 J5.A3 J5.B1 J5.B2 J5.B3
P12V_PSU: C466.1 C467.1 J6.6
85OHM_BOT_5INCH_DN: U39.1 U41.2
85OHM_BOT_5INCH_DP: U39.2 U41.1
85OHM_BOT_10INCH_DN: U43.1 U45.2
85OHM_BOT_10INCH_DP: U43.2 U45.1
85OHM_L2_5INCH_DN: U25.1 U29.2
85OHM_L2_5INCH_DP: U25.2 U29.1
85OHM_L2_10INCH_DN: U33.1 U37.2
85OHM_L2_10INCH_DP: U33.2 U37.1
85OHM_TOP_5INCH_DN: U5.1 U26.2
85OHM_TOP_5INCH_DP: U5.2 U26.1
85OHM_TOP_10INCH_DN: U30.1 U34.2
85OHM_TOP_10INCH_DP: U30.2 U34.1
AT24C64_A0: R281.2(B) R282.1 U7.1
AT24C64_A1: R283.2(B) R284.1 U7.2
AT24C64_A2: R285.2(B) R286.1 U7.3
CLK_100M_CPU1_PE_FG_DN: J5.A14 U9.7
CLK_100M_CPU1_PE_FG_DP: J5.A13 U9.6
CLK_100M_PEX8796_DN: R127.1 U9.24
CLK_100M_PEX8796_DP: R126.1 U9.23
CLK_100M_PEX8796_R_DN: R127.2(B) U1.W2
CLK_100M_PEX8796_R_DP: R126.2(B) U1.W3
CLK_100M_SLOT1_DN: R340.1 U9.15
CLK_100M_SLOT1_DP: R143.1 U9.14
CLK_100M_SLOT1_R_DN: J1.A14 R340.2(B)
CLK_100M_SLOT1_R_DP: J1.A13 R143.2(B)
CLK_100M_SLOT2_DN: R125.1 U9.18
CLK_100M_SLOT2_DP: R124.1 U9.17
CLK_100M_SLOT2_R_DN: J2.A14 R125.2(B)
CLK_100M_SLOT2_R_DP: J2.A13 R124.2(B)
CLK_100M_SLOT3_DN: R123.1 U9.27
CLK_100M_SLOT3_DP: R122.1 U9.26
CLK_100M_SLOT3_R_DN: J3.A14 R123.2(B)
CLK_100M_SLOT3_R_DP: J3.A13 R122.2(B)
CLK_BUF_CKPWRGD: Q4.D R4.2(B) U9.3
CLK_BUF_HIBW_BYPM_LOBW_N: R1.2(B) R2.1 U9.2
CPLD_PWRBRK_BUF_N: R310.1 U8.4(Y) U19.2 U20.2 U47.2
CPLD_PWRBRK_N: J5.B30 R309.2(B) U8.2
CPLD_SLOT1_PWRBRK_N: R39.1 R40.1 R164.2(B) U47.4(Y)
CPLD_SLOT1_PWRBRK_R1_N: J1.B12 R39.2(B)
CPLD_SLOT1_PWRBRK_R2_N: J1.B30 R40.2(B)
CPLD_SLOT2_PWRBRK_N: R154.2(B) R216.1 R221.1 U20.4(Y)
CPLD_SLOT2_PWRBRK_R1_N: J2.B12 R216.2(B)
CPLD_SLOT2_PWRBRK_R2_N: J2.B30 R221.2(B)
CPLD_SLOT3_PWRBRK_N: R155.2(B) R214.1 R215.1 U19.4(Y)
CPLD_SLOT3_PWRBRK_R1_N: J3.B12 R214.2(B)
CPLD_SLOT3_PWRBRK_R2_N: J3.B30 R215.2(B)
DC_PEX8747_AA18: U1.AA18
DC_PEX8747_AA21: U1.AA21
DC_PEX8747_AD18: U1.AD18
DC_PEX8747_AD21: U1.AD21
DC_PEX8747_B9: U1.B9
DC_PEX8747_B15: U1.B15
DC_PEX8747_B21: U1.B21
DC_PEX8747_F13: U1.F13
DC_PEX8747_F16: U1.F16
DC_PEX8747_F17: U1.F17
DC_PEX8747_F20: U1.F20
DC_PEX8747_F21: U1.F21
DC_PEX8747_F23: U1.F23
DC_PEX8747_H14: U1.H14
DC_PEX8747_N22: U1.N22
DC_PEX8747_P6: U1.P6
DC_PEX8747_P7: U1.P7
DC_PEX8747_P17: U1.P17
DC_PEX8747_P18: U1.P18
DC_PEX8747_T19: U1.T19
DC_PEX8747_V8: U1.V8
DC_PEX8747_W8: U1.W8
DC_PEX8747_W13: U1.W13
DC_PEX8747_Y16: U1.Y16
DC_PEX8747_Y17: U1.Y17
DC_PEX8747_Y19: U1.Y19
DC_PEX8747_Y20: U1.Y20
DC_PEX8747_Y22: U1.Y22
EMC1413_ADDR: R150.2(B) U10.7
EMC1413_ALERT_N: R151.2(B) U10.8
I2C_ADDR0: R94.2(B) R108.1 U1.F5
I2C_MUX_ADD_A0: R83.2(B) R84.1 U2.1
I2C_MUX_ADD_A1: R81.2(B) R82.1 U2.2
I2C_MUX_ADD_A2: R79.2(B) R80.1 U2.21
I2C_MUX_RST_N: R78.2(B) U2.3
I2C_PCA9548_SC1_SLOT3_R_SCL: R22.1 U2.7
I2C_PCA9548_SC1_SLOT3_SCL: Q15.D R22.2(B) R98.2(B) R226.1
I2C_PCA9548_SC3_SLOT2_R_SCL: R26.1 U2.11
I2C_PCA9548_SC3_SLOT2_SCL: Q21.D R26.2(B) R102.2(B) R228.1
I2C_PCA9548_SC4_SLOT1_R_SCL: R339.1 U2.14
I2C_PCA9548_SC4_SLOT1_SCL: Q20.D R145.2(B) R307.1 R339.2(B)
I2C_PCA9548_SC5_3V3_PE_SCL: CON1.2 Q25.S R194.2(B) R234.2(B) U12.7
I2C_PCA9548_SC5_P1V8_SCL: R277.2(B) U1.F7 U12.2
I2C_PCA9548_SC5_PE_R_SCL: R28.1 U2.16
I2C_PCA9548_SC5_PE_SCL: Q25.D R28.2(B) R104.2(B) R234.1
I2C_PCA9548_SC6_3V3_CLK_R_SCL: R90.2(B) U9.9
I2C_PCA9548_SC6_3V3_CLK_SCL: Q19.S R90.1 R193.2(B) R236.2(B)
I2C_PCA9548_SC6_CLK_R_SCL: R30.1 U2.18
I2C_PCA9548_SC6_CLK_SCL: Q19.D R30.2(B) R106.2(B) R183.1 R236.1 R280.2(B) R299.1
I2C_PCA9548_SC6_FRU_SCL: R280.1 U7.6
I2C_PCA9548_SC6_SEN1_SCL: R183.2(B) U10.10
I2C_PCA9548_SC6_SEN2_SCL: R299.2(B) U4.8
I2C_PCA9548_SC7_ADC128_R_SCL: R142.1 U2.20
I2C_PCA9548_SC7_ADC128_SCL: R142.2(B) R157.2(B) R186.2(B)
I2C_PCA9548_SC7_ADC128_SCL_R: R157.1 U3.10
I2C_PCA9548_SD1_SLOT3_R_SDA: R21.1 U2.6
I2C_PCA9548_SD1_SLOT3_SDA: Q18.D R21.2(B) R97.2(B) R227.1
I2C_PCA9548_SD3_SLOT2_R_SDA: R25.1 U2.10
I2C_PCA9548_SD3_SLOT2_SDA: Q24.D R25.2(B) R101.2(B) R233.1
I2C_PCA9548_SD4_SLOT1_R_SDA: R338.1 U2.13
I2C_PCA9548_SD4_SLOT1_SDA: Q23.D R144.2(B) R308.1 R338.2(B)
I2C_PCA9548_SD5_3V3_PE_SDA: CON1.3 Q26.S R209.2(B) R235.2(B) U12.6
I2C_PCA9548_SD5_P1V8_SDA: R278.2(B) U1.F2 U12.3
I2C_PCA9548_SD5_PE_R_SDA: R27.1 U2.15
I2C_PCA9548_SD5_PE_SDA: Q26.D R27.2(B) R103.2(B) R235.1
I2C_PCA9548_SD6_3V3_CLK_R_SDA: R89.2(B) U9.8
I2C_PCA9548_SD6_3V3_CLK_SDA: Q22.S R89.1 R204.2(B) R237.2(B)
I2C_PCA9548_SD6_CLK_R_SDA: R29.1 U2.17
I2C_PCA9548_SD6_CLK_SDA: Q22.D R29.2(B) R105.2(B) R184.1 R237.1 R279.2(B) R300.1
I2C_PCA9548_SD6_FRU_SDA: R279.1 U7.5
I2C_PCA9548_SD6_SEN1_SDA: R184.2(B) U10.9
I2C_PCA9548_SD6_SEN2_SDA: R300.2(B) U4.7
I2C_PCA9548_SD7_ADC128_R_SDA: R141.1 U2.19
I2C_PCA9548_SD7_ADC128_SDA: R141.2(B) R158.2(B) R185.2(B)
I2C_PCA9548_SD7_ADC128_SDA_R: R158.1 U3.9
I2C_PE_SCL: J5.B5 R86.1
I2C_PE_SCL_R: R86.2(B) R87.2(B) U2.22
I2C_PE_SDA: J5.B6 R85.1
I2C_PE_SDA_R: R85.2(B) R88.2(B) U2.23
I2C_SC5_2N7002_G_SCL: Q25.G R161.2(B)
I2C_SC6_2N7002_G_SCL: Q19.G R160.2(B)
I2C_SD5_2N7002_G_SDA: Q26.G R191.2(B)
I2C_SD6_2N7002_G_SDA: Q22.G R163.2(B)
I2C_SLOT1_2N7002_G_SCL: Q20.G R301.2(B)
I2C_SLOT1_2N7002_G_SDA: Q23.G R342.2(B)
I2C_SLOT1_3V3_SCL: J1.B5 Q20.S R303.2(B) R307.2(B)
I2C_SLOT1_3V3_SDA: J1.B6 Q23.S R304.2(B) R308.2(B)
I2C_SLOT2_2N7002_G_SCL: Q21.G R162.2(B)
I2C_SLOT2_2N7002_G_SDA: Q24.G R192.2(B)
I2C_SLOT2_3V3_SCL: J2.B5 Q21.S R203.2(B) R228.2(B)
I2C_SLOT2_3V3_SDA: J2.B6 Q24.S R210.2(B) R233.2(B)
I2C_SLOT3_2N7002_G_SCL: Q15.G R107.2(B)
I2C_SLOT3_2N7002_G_SDA: Q18.G R153.2(B)
I2C_SLOT3_3V3_SCL: J3.B5 Q15.S R156.2(B) R226.2(B)
I2C_SLOT3_3V3_SDA: J3.B6 Q18.S R159.2(B) R227.2(B)
JTAG_R_TCK: J1.A5 R306.1
JTAG_R_TDI: J1.A6 R347.1
JTAG_R_TDO: J1.A7 R354.1
JTAG_R_TMS: J1.A8 R355.1
JTAG_TCK: J5.A5 R306.2(B) R358.2(B)
JTAG_TDI: J5.A6 R347.2(B) R359.2(B)
JTAG_TDO: J5.A7 R354.2(B) R357.2(B)
JTAG_TMS: J5.A8 R355.2(B) R356.2(B)
JTAG_TRST_N: J1.B9 J5.B9 R360.2(B)
NC_CLK_100M_4_DN: U9.34
NC_CLK_100M_4_DP: U9.33
NC_CLK_100M_5_DN: U9.37
NC_CLK_100M_5_DP: U9.36
NC_CLK_BUF_DFBOUT_DN: U9.10
NC_CLK_BUF_DFBOUT_DP: U9.11
NC_CLK_BUF_NC: U9.30
NC_CLK_BUF_NC_1: U9.40
NC_JTAG_TCK: U1.G11
NC_JTAG_TDI: U1.J6
NC_JTAG_TDO: U1.F11
NC_JTAG_TMS: U1.H11
NC_P0V9_VP: PU23.16
NC_P3V3_VP: PU17.16
NC_PEX_FATAL_ERR_N: U1.F14
NC_PEX_INTA_N: U1.B6
PCA9617_EN: R276.1 R296.2(B) U12.5
PCIE_SLOT1_WAKE_N: J1.B11 R370.2(B)
PCIE_SLOT2_WAKE_N: J2.B11 R8.2(B)
PCIE_SLOT3_WAKE_N: J3.B11 R7.2(B)
PCIE_SLOT_PRES_N: J1.A1 J5.A1 R5.2(B) R9.2(B) R34.2(B) R77.2(B) R165.1
PCIE_X1_SLOT1_PRES_N: J1.B17 R165.2(B) R166.2(B)
PCIE_X1_SLOT_PRES_N: J5.B17 R9.1 R166.1
PCIE_X4_SLOT_PRES_N: J1.B31 J5.B31 R34.1
PCIE_X8_SLOT_PRES_N: J1.B48 J5.B48 R77.1
PCIE_X16_SLOT_PRES_N: J1.B81 J5.B81 R5.1
PD_FRU_WP: R293.2(B) R294.1 U7.7(WP)
PD_JTAG_TRST_N: R10.1 U1.F3
PD_REXT_A0: R11.1 U1.W11
PD_REXT_A1: R12.1 U1.Y11
PD_REXT_A2: R13.1 U1.Y14
PD_REXT_A3: R14.1 U1.W16
PD_REXT_A4: R15.1 U1.N2
PD_REXT_A5: R16.1 U1.G7
PD_REXT_A6: R17.1 U1.F8
PD_REXT_A7: R18.1 U1.F10
PD_REXT_A8: R19.1 U1.T21
PD_REXT_A9: R20.1 U1.K22
PD_REXT_A10: R23.1 U1.G14
PD_REXT_A11: R24.1 U1.G13
PD_REXT_B0: R31.1 U1.Y10
PD_REXT_B1: R32.1 U1.V10
PD_REXT_B2: R33.1 U1.Y13
PD_REXT_B3: R132.1 U1.W15
PD_REXT_B4: R35.1 U1.W7
PD_REXT_B5: R36.1 U1.L6
PD_REXT_B6: R37.1 U1.G8
PD_REXT_B7: R38.1 U1.G10
PD_REXT_B8: R133.1 U1.T22
PD_REXT_B9: R134.1 U1.G17
PD_REXT_B10: R41.1 U1.G16
PD_REXT_B11: R42.1 U1.H13
PD_REXT_CMU: R43.1 U1.W10
PD_SLOT2_A1: J2.A1 R200.1
PD_SLOT3_A1: J3.A1 R199.1
PD_VOE_N: R76.2(B) U9.13 U9.19 U9.22 U9.28
PE_CPU_RX_DN<0>: J1.A17 J5.A17
PE_CPU_RX_DN<1>: J1.A22 J5.A22
PE_CPU_RX_DN<2>: J1.A26 J5.A26
PE_CPU_RX_DN<3>: J1.A30 J5.A30
PE_CPU_RX_DN<4>: J1.A36 J5.A36
PE_CPU_RX_DN<5>: J1.A40 J5.A40
PE_CPU_RX_DN<6>: J1.A44 J5.A44
PE_CPU_RX_DN<7>: J1.A48 J5.A48
PE_CPU_RX_DN<8>: J1.A53 J5.A53
PE_CPU_RX_DN<9>: J1.A57 J5.A57
PE_CPU_RX_DN<10>: J1.A61 J5.A61
PE_CPU_RX_DN<11>: J1.A65 J5.A65
PE_CPU_RX_DN<12>: J1.A69 J5.A69
PE_CPU_RX_DN<13>: J1.A73 J5.A73
PE_CPU_RX_DN<14>: J1.A77 J5.A77
PE_CPU_RX_DN<15>: J1.A81 J5.A81
PE_CPU_RX_DP<0>: J1.A16 J5.A16
PE_CPU_RX_DP<1>: J1.A21 J5.A21
PE_CPU_RX_DP<2>: J1.A25 J5.A25
PE_CPU_RX_DP<3>: J1.A29 J5.A29
PE_CPU_RX_DP<4>: J1.A35 J5.A35
PE_CPU_RX_DP<5>: J1.A39 J5.A39
PE_CPU_RX_DP<6>: J1.A43 J5.A43
PE_CPU_RX_DP<7>: J1.A47 J5.A47
PE_CPU_RX_DP<8>: J1.A52 J5.A52
PE_CPU_RX_DP<9>: J1.A56 J5.A56
PE_CPU_RX_DP<10>: J1.A60 J5.A60
PE_CPU_RX_DP<11>: J1.A64 J5.A64
PE_CPU_RX_DP<12>: J1.A68 J5.A68
PE_CPU_RX_DP<13>: J1.A72 J5.A72
PE_CPU_RX_DP<14>: J1.A76 J5.A76
PE_CPU_RX_DP<15>: J1.A80 J5.A80
PE_CPU_TX_DN<0>: J1.B15 J5.B15
PE_CPU_TX_DN<1>: J1.B20 J5.B20
PE_CPU_TX_DN<2>: J1.B24 J5.B24
PE_CPU_TX_DN<3>: J1.B28 J5.B28
PE_CPU_TX_DN<4>: J1.B34 J5.B34
PE_CPU_TX_DN<5>: J1.B38 J5.B38
PE_CPU_TX_DN<6>: J1.B42 J5.B42
PE_CPU_TX_DN<7>: J1.B46 J5.B46
PE_CPU_TX_DN<8>: J1.B51 J5.B51
PE_CPU_TX_DN<9>: J1.B55 J5.B55
PE_CPU_TX_DN<10>: J1.B59 J5.B59
PE_CPU_TX_DN<11>: J1.B63 J5.B63
PE_CPU_TX_DN<12>: J1.B67 J5.B67
PE_CPU_TX_DN<13>: J1.B71 J5.B71
PE_CPU_TX_DN<14>: J1.B75 J5.B75
PE_CPU_TX_DN<15>: J1.B79 J5.B79
PE_CPU_TX_DP<0>: J1.B14 J5.B14
PE_CPU_TX_DP<1>: J1.B19 J5.B19
PE_CPU_TX_DP<2>: J1.B23 J5.B23
PE_CPU_TX_DP<3>: J1.B27 J5.B27
PE_CPU_TX_DP<4>: J1.B33 J5.B33
PE_CPU_TX_DP<5>: J1.B37 J5.B37
PE_CPU_TX_DP<6>: J1.B41 J5.B41
PE_CPU_TX_DP<7>: J1.B45 J5.B45
PE_CPU_TX_DP<8>: J1.B50 J5.B50
PE_CPU_TX_DP<9>: J1.B54 J5.B54
PE_CPU_TX_DP<10>: J1.B58 J5.B58
PE_CPU_TX_DP<11>: J1.B62 J5.B62
PE_CPU_TX_DP<12>: J1.B66 J5.B66
PE_CPU_TX_DP<13>: J1.B70 J5.B70
PE_CPU_TX_DP<14>: J1.B74 J5.B74
PE_CPU_TX_DP<15>: J1.B78 J5.B78
PE_SLOT2_PRES_N: J2.B81 R44.2(B)
PE_SLOT2_RX_DN<0>: J2.A17 U1.D11
PE_SLOT2_RX_DN<1>: J2.A22 U1.D10
PE_SLOT2_RX_DN<2>: J2.A26 U1.D8
PE_SLOT2_RX_DN<3>: J2.A30 U1.D7
PE_SLOT2_RX_DN<4>: J2.A36 U1.D5
PE_SLOT2_RX_DN<5>: J2.A40 U1.D4
PE_SLOT2_RX_DN<6>: J2.A44 U1.D2
PE_SLOT2_RX_DN<7>: J2.A48 U1.D1
PE_SLOT2_RX_DN<8>: J2.A53 U1.H4
PE_SLOT2_RX_DN<9>: J2.A57 U1.J4
PE_SLOT2_RX_DN<10>: J2.A61 U1.L4
PE_SLOT2_RX_DN<11>: J2.A65 U1.M4
PE_SLOT2_RX_DN<12>: J2.A69 U1.P4
PE_SLOT2_RX_DN<13>: J2.A73 U1.R4
PE_SLOT2_RX_DN<14>: J2.A77 U1.U5
PE_SLOT2_RX_DN<15>: J2.A81 U1.V5
PE_SLOT2_RX_DP<0>: J2.A16 U1.E11
PE_SLOT2_RX_DP<1>: J2.A21 U1.E10
PE_SLOT2_RX_DP<2>: J2.A25 U1.E8
PE_SLOT2_RX_DP<3>: J2.A29 U1.E7
PE_SLOT2_RX_DP<4>: J2.A35 U1.E5
PE_SLOT2_RX_DP<5>: J2.A39 U1.E4
PE_SLOT2_RX_DP<6>: J2.A43 U1.E2
PE_SLOT2_RX_DP<7>: J2.A47 U1.E1
PE_SLOT2_RX_DP<8>: J2.A52 U1.H5
PE_SLOT2_RX_DP<9>: J2.A56 U1.J5
PE_SLOT2_RX_DP<10>: J2.A60 U1.L5
PE_SLOT2_RX_DP<11>: J2.A64 U1.M5
PE_SLOT2_RX_DP<12>: J2.A68 U1.P5
PE_SLOT2_RX_DP<13>: J2.A72 U1.R5
PE_SLOT2_RX_DP<14>: J2.A76 U1.U4
PE_SLOT2_RX_DP<15>: J2.A80 U1.V4
PE_SLOT2_TX_C_DN<0>: C31.1 U1.A11
PE_SLOT2_TX_C_DN<1>: C32.1 U1.A10
PE_SLOT2_TX_C_DN<2>: C33.1 U1.A8
PE_SLOT2_TX_C_DN<3>: C34.1 U1.A7
PE_SLOT2_TX_C_DN<4>: C67.1 U1.A5
PE_SLOT2_TX_C_DN<5>: C68.1 U1.A4
PE_SLOT2_TX_C_DN<6>: C69.1 U1.A2
PE_SLOT2_TX_C_DN<7>: C70.1 U1.A1
PE_SLOT2_TX_C_DN<8>: C71.1 U1.H1
PE_SLOT2_TX_C_DN<9>: C72.1 U1.J1
PE_SLOT2_TX_C_DN<10>: C73.1 U1.L1
PE_SLOT2_TX_C_DN<11>: C74.1 U1.M1
PE_SLOT2_TX_C_DN<12>: C75.1 U1.P1
PE_SLOT2_TX_C_DN<13>: C76.1 U1.R1
PE_SLOT2_TX_C_DN<14>: C77.1 U1.U1
PE_SLOT2_TX_C_DN<15>: C78.1 U1.V1
PE_SLOT2_TX_C_DP<0>: C27.1 U1.B11
PE_SLOT2_TX_C_DP<1>: C28.1 U1.B10
PE_SLOT2_TX_C_DP<2>: C29.1 U1.B8
PE_SLOT2_TX_C_DP<3>: C30.1 U1.B7
PE_SLOT2_TX_C_DP<4>: C55.1 U1.B5
PE_SLOT2_TX_C_DP<5>: C56.1 U1.B4
PE_SLOT2_TX_C_DP<6>: C57.1 U1.B2
PE_SLOT2_TX_C_DP<7>: C58.1 U1.B1
PE_SLOT2_TX_C_DP<8>: C59.1 U1.H2
PE_SLOT2_TX_C_DP<9>: C60.1 U1.J2
PE_SLOT2_TX_C_DP<10>: C61.1 U1.L2
PE_SLOT2_TX_C_DP<11>: C62.1 U1.M2
PE_SLOT2_TX_C_DP<12>: C63.1 U1.P2
PE_SLOT2_TX_C_DP<13>: C64.1 U1.R2
PE_SLOT2_TX_C_DP<14>: C65.1 U1.U2
PE_SLOT2_TX_C_DP<15>: C66.1 U1.V2
PE_SLOT2_TX_DN<0>: C31.2(B) J2.B15
PE_SLOT2_TX_DN<1>: C32.2(B) J2.B20
PE_SLOT2_TX_DN<2>: C33.2(B) J2.B24
PE_SLOT2_TX_DN<3>: C34.2(B) J2.B28
PE_SLOT2_TX_DN<4>: C67.2(B) J2.B34
PE_SLOT2_TX_DN<5>: C68.2(B) J2.B38
PE_SLOT2_TX_DN<6>: C69.2(B) J2.B42
PE_SLOT2_TX_DN<7>: C70.2(B) J2.B46
PE_SLOT2_TX_DN<8>: C71.2(B) J2.B51
PE_SLOT2_TX_DN<9>: C72.2(B) J2.B55
PE_SLOT2_TX_DN<10>: C73.2(B) J2.B59
PE_SLOT2_TX_DN<11>: C74.2(B) J2.B63
PE_SLOT2_TX_DN<12>: C75.2(B) J2.B67
PE_SLOT2_TX_DN<13>: C76.2(B) J2.B71
PE_SLOT2_TX_DN<14>: C77.2(B) J2.B75
PE_SLOT2_TX_DN<15>: C78.2(B) J2.B79
PE_SLOT2_TX_DP<0>: C27.2(B) J2.B14
PE_SLOT2_TX_DP<1>: C28.2(B) J2.B19
PE_SLOT2_TX_DP<2>: C29.2(B) J2.B23
PE_SLOT2_TX_DP<3>: C30.2(B) J2.B27
PE_SLOT2_TX_DP<4>: C55.2(B) J2.B33
PE_SLOT2_TX_DP<5>: C56.2(B) J2.B37
PE_SLOT2_TX_DP<6>: C57.2(B) J2.B41
PE_SLOT2_TX_DP<7>: C58.2(B) J2.B45
PE_SLOT2_TX_DP<8>: C59.2(B) J2.B50
PE_SLOT2_TX_DP<9>: C60.2(B) J2.B54
PE_SLOT2_TX_DP<10>: C61.2(B) J2.B58
PE_SLOT2_TX_DP<11>: C62.2(B) J2.B62
PE_SLOT2_TX_DP<12>: C63.2(B) J2.B66
PE_SLOT2_TX_DP<13>: C64.2(B) J2.B70
PE_SLOT2_TX_DP<14>: C65.2(B) J2.B74
PE_SLOT2_TX_DP<15>: C66.2(B) J2.B78
PE_SLOT3_PRES_N: J3.B81 R45.2(B)
PE_SLOT3_RX_DN<0>: J3.A17 U1.V20
PE_SLOT3_RX_DN<1>: J3.A22 U1.U20
PE_SLOT3_RX_DN<2>: J3.A26 U1.R20
PE_SLOT3_RX_DN<3>: J3.A30 U1.P20
PE_SLOT3_RX_DN<4>: J3.A36 U1.M20
PE_SLOT3_RX_DN<5>: J3.A40 U1.L20
PE_SLOT3_RX_DN<6>: J3.A44 U1.J20
PE_SLOT3_RX_DN<7>: J3.A48 U1.H20
PE_SLOT3_RX_DN<8>: J3.A53 U1.D23
PE_SLOT3_RX_DN<9>: J3.A57 U1.D22
PE_SLOT3_RX_DN<10>: J3.A61 U1.D20
PE_SLOT3_RX_DN<11>: J3.A65 U1.D19
PE_SLOT3_RX_DN<12>: J3.A69 U1.D17
PE_SLOT3_RX_DN<13>: J3.A73 U1.D16
PE_SLOT3_RX_DN<14>: J3.A77 U1.D14
PE_SLOT3_RX_DN<15>: J3.A81 U1.D13
PE_SLOT3_RX_DP<0>: J3.A16 U1.V19
PE_SLOT3_RX_DP<1>: J3.A21 U1.U19
PE_SLOT3_RX_DP<2>: J3.A25 U1.R19
PE_SLOT3_RX_DP<3>: J3.A29 U1.P19
PE_SLOT3_RX_DP<4>: J3.A35 U1.M19
PE_SLOT3_RX_DP<5>: J3.A39 U1.L19
PE_SLOT3_RX_DP<6>: J3.A43 U1.J19
PE_SLOT3_RX_DP<7>: J3.A47 U1.H19
PE_SLOT3_RX_DP<8>: J3.A52 U1.E23
PE_SLOT3_RX_DP<9>: J3.A56 U1.E22
PE_SLOT3_RX_DP<10>: J3.A60 U1.E20
PE_SLOT3_RX_DP<11>: J3.A64 U1.E19
PE_SLOT3_RX_DP<12>: J3.A68 U1.E17
PE_SLOT3_RX_DP<13>: J3.A72 U1.E16
PE_SLOT3_RX_DP<14>: J3.A76 U1.E14
PE_SLOT3_RX_DP<15>: J3.A80 U1.E13
PE_SLOT3_TX_C_DN<0>: C43.1 U1.V23
PE_SLOT3_TX_C_DN<1>: C44.1 U1.U23
PE_SLOT3_TX_C_DN<2>: C45.1 U1.R23
PE_SLOT3_TX_C_DN<3>: C46.1 U1.P23
PE_SLOT3_TX_C_DN<4>: C115.1 U1.M23
PE_SLOT3_TX_C_DN<5>: C116.1 U1.L23
PE_SLOT3_TX_C_DN<6>: C117.1 U1.J23
PE_SLOT3_TX_C_DN<7>: C118.1 U1.H23
PE_SLOT3_TX_C_DN<8>: C119.1 U1.A23
PE_SLOT3_TX_C_DN<9>: C120.1 U1.A22
PE_SLOT3_TX_C_DN<10>: C121.1 U1.A20
PE_SLOT3_TX_C_DN<11>: C122.1 U1.A19
PE_SLOT3_TX_C_DN<12>: C123.1 U1.A17
PE_SLOT3_TX_C_DN<13>: C124.1 U1.A16
PE_SLOT3_TX_C_DN<14>: C125.1 U1.A14
PE_SLOT3_TX_C_DN<15>: C126.1 U1.A13
PE_SLOT3_TX_C_DP<0>: C39.1 U1.V22
PE_SLOT3_TX_C_DP<1>: C40.1 U1.U22
PE_SLOT3_TX_C_DP<2>: C41.1 U1.R22
PE_SLOT3_TX_C_DP<3>: C42.1 U1.P22
PE_SLOT3_TX_C_DP<4>: C103.1 U1.M22
PE_SLOT3_TX_C_DP<5>: C104.1 U1.L22
PE_SLOT3_TX_C_DP<6>: C105.1 U1.J22
PE_SLOT3_TX_C_DP<7>: C106.1 U1.H22
PE_SLOT3_TX_C_DP<8>: C107.1 U1.B23
PE_SLOT3_TX_C_DP<9>: C108.1 U1.B22
PE_SLOT3_TX_C_DP<10>: C109.1 U1.B20
PE_SLOT3_TX_C_DP<11>: C110.1 U1.B19
PE_SLOT3_TX_C_DP<12>: C111.1 U1.B17
PE_SLOT3_TX_C_DP<13>: C112.1 U1.B16
PE_SLOT3_TX_C_DP<14>: C113.1 U1.B14
PE_SLOT3_TX_C_DP<15>: C114.1 U1.B13
PE_SLOT3_TX_DN<0>: C43.2(B) J3.B15
PE_SLOT3_TX_DN<1>: C44.2(B) J3.B20
PE_SLOT3_TX_DN<2>: C45.2(B) J3.B24
PE_SLOT3_TX_DN<3>: C46.2(B) J3.B28
PE_SLOT3_TX_DN<4>: C115.2(B) J3.B34
PE_SLOT3_TX_DN<5>: C116.2(B) J3.B38
PE_SLOT3_TX_DN<6>: C117.2(B) J3.B42
PE_SLOT3_TX_DN<7>: C118.2(B) J3.B46
PE_SLOT3_TX_DN<8>: C119.2(B) J3.B51
PE_SLOT3_TX_DN<9>: C120.2(B) J3.B55
PE_SLOT3_TX_DN<10>: C121.2(B) J3.B59
PE_SLOT3_TX_DN<11>: C122.2(B) J3.B63
PE_SLOT3_TX_DN<12>: C123.2(B) J3.B67
PE_SLOT3_TX_DN<13>: C124.2(B) J3.B71
PE_SLOT3_TX_DN<14>: C125.2(B) J3.B75
PE_SLOT3_TX_DN<15>: C126.2(B) J3.B79
PE_SLOT3_TX_DP<0>: C39.2(B) J3.B14
PE_SLOT3_TX_DP<1>: C40.2(B) J3.B19
PE_SLOT3_TX_DP<2>: C41.2(B) J3.B23
PE_SLOT3_TX_DP<3>: C42.2(B) J3.B27
PE_SLOT3_TX_DP<4>: C103.2(B) J3.B33
PE_SLOT3_TX_DP<5>: C104.2(B) J3.B37
PE_SLOT3_TX_DP<6>: C105.2(B) J3.B41
PE_SLOT3_TX_DP<7>: C106.2(B) J3.B45
PE_SLOT3_TX_DP<8>: C107.2(B) J3.B50
PE_SLOT3_TX_DP<9>: C108.2(B) J3.B54
PE_SLOT3_TX_DP<10>: C109.2(B) J3.B58
PE_SLOT3_TX_DP<11>: C110.2(B) J3.B62
PE_SLOT3_TX_DP<12>: C111.2(B) J3.B66
PE_SLOT3_TX_DP<13>: C112.2(B) J3.B70
PE_SLOT3_TX_DP<14>: C113.2(B) J3.B74
PE_SLOT3_TX_DP<15>: C114.2(B) J3.B78
PE_SLV_RX_C_DN<0>: C35.1 U1.AB1
PE_SLV_RX_C_DN<1>: C36.1 U1.AB2
PE_SLV_RX_C_DN<2>: C37.1 U1.AB4
PE_SLV_RX_C_DN<3>: C38.1 U1.AB5
PE_SLV_RX_C_DN<4>: C91.1 U1.AB7
PE_SLV_RX_C_DN<5>: C92.1 U1.AB8
PE_SLV_RX_C_DN<6>: C93.1 U1.AB10
PE_SLV_RX_C_DN<7>: C94.1 U1.AB11
PE_SLV_RX_C_DN<8>: C95.1 U1.AB13
PE_SLV_RX_C_DN<9>: C96.1 U1.AB14
PE_SLV_RX_C_DN<10>: C97.1 U1.AB16
PE_SLV_RX_C_DN<11>: C98.1 U1.AB17
PE_SLV_RX_C_DN<12>: C99.1 U1.AB19
PE_SLV_RX_C_DN<13>: C100.1 U1.AB20
PE_SLV_RX_C_DN<14>: C101.1 U1.AB22
PE_SLV_RX_C_DN<15>: C102.1 U1.AB23
PE_SLV_RX_C_DP<0>: C23.1 U1.AA1
PE_SLV_RX_C_DP<1>: C24.1 U1.AA2
PE_SLV_RX_C_DP<2>: C25.1 U1.AA4
PE_SLV_RX_C_DP<3>: C26.1 U1.AA5
PE_SLV_RX_C_DP<4>: C79.1 U1.AA7
PE_SLV_RX_C_DP<5>: C80.1 U1.AA8
PE_SLV_RX_C_DP<6>: C81.1 U1.AA10
PE_SLV_RX_C_DP<7>: C82.1 U1.AA11
PE_SLV_RX_C_DP<8>: C83.1 U1.AA13
PE_SLV_RX_C_DP<9>: C84.1 U1.AA14
PE_SLV_RX_C_DP<10>: C85.1 U1.AA16
PE_SLV_RX_C_DP<11>: C86.1 U1.AA17
PE_SLV_RX_C_DP<12>: C87.1 U1.AA19
PE_SLV_RX_C_DP<13>: C88.1 U1.AA20
PE_SLV_RX_C_DP<14>: C89.1 U1.AA22
PE_SLV_RX_C_DP<15>: C90.1 U1.AA23
PE_SLV_RX_DN<0>: C35.2(B) J7.3
PE_SLV_RX_DN<1>: C36.2(B) J7.6
PE_SLV_RX_DN<2>: C37.2(B) J7.9
PE_SLV_RX_DN<3>: C38.2(B) J7.12
PE_SLV_RX_DN<4>: C91.2(B) J7.15
PE_SLV_RX_DN<5>: C92.2(B) J7.18
PE_SLV_RX_DN<6>: C93.2(B) J7.21
PE_SLV_RX_DN<7>: C94.2(B) J7.24
PE_SLV_RX_DN<8>: C95.2(B) J8.3
PE_SLV_RX_DN<9>: C96.2(B) J8.6
PE_SLV_RX_DN<10>: C97.2(B) J8.9
PE_SLV_RX_DN<11>: C98.2(B) J8.12
PE_SLV_RX_DN<12>: C99.2(B) J8.15
PE_SLV_RX_DN<13>: C100.2(B) J8.18
PE_SLV_RX_DN<14>: C101.2(B) J8.21
PE_SLV_RX_DN<15>: C102.2(B) J8.24
PE_SLV_RX_DP<0>: C23.2(B) J7.2
PE_SLV_RX_DP<1>: C24.2(B) J7.5
PE_SLV_RX_DP<2>: C25.2(B) J7.8
PE_SLV_RX_DP<3>: C26.2(B) J7.11
PE_SLV_RX_DP<4>: C79.2(B) J7.14
PE_SLV_RX_DP<5>: C80.2(B) J7.17
PE_SLV_RX_DP<6>: C81.2(B) J7.20
PE_SLV_RX_DP<7>: C82.2(B) J7.23
PE_SLV_RX_DP<8>: C83.2(B) J8.2
PE_SLV_RX_DP<9>: C84.2(B) J8.5
PE_SLV_RX_DP<10>: C85.2(B) J8.8
PE_SLV_RX_DP<11>: C86.2(B) J8.11
PE_SLV_RX_DP<12>: C87.2(B) J8.14
PE_SLV_RX_DP<13>: C88.2(B) J8.17
PE_SLV_RX_DP<14>: C89.2(B) J8.20
PE_SLV_RX_DP<15>: C90.2(B) J8.23
PE_SLV_TX_DN<0>: J7.48 U1.AE1
PE_SLV_TX_DN<1>: J7.45 U1.AE2
PE_SLV_TX_DN<2>: J7.42 U1.AE4
PE_SLV_TX_DN<3>: J7.39 U1.AE5
PE_SLV_TX_DN<4>: J7.36 U1.AE7
PE_SLV_TX_DN<5>: J7.33 U1.AE8
PE_SLV_TX_DN<6>: J7.30 U1.AE10
PE_SLV_TX_DN<7>: J7.27 U1.AE11
PE_SLV_TX_DN<8>: J8.48 U1.AE13
PE_SLV_TX_DN<9>: J8.45 U1.AE14
PE_SLV_TX_DN<10>: J8.42 U1.AE16
PE_SLV_TX_DN<11>: J8.39 U1.AE17
PE_SLV_TX_DN<12>: J8.36 U1.AE19
PE_SLV_TX_DN<13>: J8.33 U1.AE20
PE_SLV_TX_DN<14>: J8.30 U1.AE22
PE_SLV_TX_DN<15>: J8.27 U1.AE23
PE_SLV_TX_DP<0>: J7.49 U1.AD1
PE_SLV_TX_DP<1>: J7.46 U1.AD2
PE_SLV_TX_DP<2>: J7.43 U1.AD4
PE_SLV_TX_DP<3>: J7.40 U1.AD5
PE_SLV_TX_DP<4>: J7.37 U1.AD7
PE_SLV_TX_DP<5>: J7.34 U1.AD8
PE_SLV_TX_DP<6>: J7.31 U1.AD10
PE_SLV_TX_DP<7>: J7.28 U1.AD11
PE_SLV_TX_DP<8>: J8.49 U1.AD13
PE_SLV_TX_DP<9>: J8.46 U1.AD14
PE_SLV_TX_DP<10>: J8.43 U1.AD16
PE_SLV_TX_DP<11>: J8.40 U1.AD17
PE_SLV_TX_DP<12>: J8.37 U1.AD19
PE_SLV_TX_DP<13>: J8.34 U1.AD20
PE_SLV_TX_DP<14>: J8.31 U1.AD22
PE_SLV_TX_DP<15>: J8.28 U1.AD23
PE_WAKE_N: J5.B11 R7.1 R8.1 R370.1
PEX8747_SPARE0: R93.2(B) U1.F1
PEX8747_SPARE1: R74.2(B) U1.Y2
PEX8747_SPARE2: R72.2(B) R73.1 U1.U6
PEX8747_SPARE3: R75.1 U1.K2
PEX_EEP_CS_N: R118.1 U1.K19
PEX_EEP_CS_R_N: R118.2(B) R128.2(B) U6.1
PEX_EEP_HOLD_N: R129.2(B) U6.7
PEX_EEP_SCLK: R130.2(B) U1.F22
PEX_EEP_SCLK_R: R130.1 U6.6
PEX_EEP_SI: R131.2(B) U1.F19
PEX_EEP_SI_R: R131.1 U6.5
PEX_EEP_SO: R119.1 U1.R18
PEX_EEP_SO_R: R119.2(B) R121.2(B) U6.2
PEX_GPIO1: R44.1 R47.2(B) U1.N3
PEX_GPIO2: R45.1 R48.2(B) U1.Y5
PEX_GPIO3: R49.2(B) U1.V11
PEX_GPIO6: R52.2(B) U1.Y6
PEX_GPIO7: R53.2(B) U1.M6
PEX_GPIO10: R56.2(B) U1.Y4
PEX_PERST_BUF_N: C192.1 C193.1 Q2.D R351.2(B) U13.2
PEX_PERST_N: U1.V7 U13.4(Y)
PEX_RORT_GOOD0_N: R46.2(B) U1.B3
PEX_RORT_GOOD4_N: R50.2(B) U1.T2
PEX_RORT_GOOD5_N: R51.2(B) U1.W6
PEX_RORT_GOOD8_N: R54.2(B) U1.T3
PEX_RORT_GOOD9_N: R55.2(B) U1.W5
PG_CKPWRGD_N: Q3.D Q4.G R3.2(B)
PG_MOS: Q3.G R297.2(B) R298.2(B)
PST_PE_SLOT1_N: J1.A11 R317.2(B) U11.4(Y)
PST_PE_SLOT2_N: J2.A11 R353.2(B) U17.4(Y)
PST_PE_SLOT3_N: J3.A11 R352.2(B) U16.4(Y)
PU_EEP_WP_R_N: R120.2(B) U6.3(WP)
PU_EMC1412_ALERT: R341.2(B) U4.6
PU_EMC1412_TEM: R302.2(B) U4.4
PU_PCA9548_SC0: R96.2(B) U2.5
PU_PCA9548_SC2: R100.2(B) U2.9
PU_PCA9548_SD0: R95.2(B) U2.4
PU_PCA9548_SD2: R99.2(B) U2.8
PU_VOE4_N: R6.2(B) U9.32
PU_VOE5_N: R137.2(B) U9.38(VOE5*)
RST_PE_SLOT_N: J5.A11 Q1.G U11.2 U16.2 U17.2
RST_PEX_MOS_N: Q1.D Q2.G R348.2(B)
SLOT2_JTAG_TCK: J2.A5 R275.2(B)
SLOT2_JTAG_TDI: J2.A6 R262.2(B)
SLOT2_JTAG_TDO: J2.A7 R263.2(B)
SLOT2_JTAG_TMS: J2.A8 R264.2(B)
SLOT2_JTAG_TRST_N: J2.B9 R261.2(B)
SLOT3_JTAG_TCK: J3.A5 R260.2(B)
SLOT3_JTAG_TDI: J3.A6 R257.2(B)
SLOT3_JTAG_TDO: J3.A7 R258.2(B)
SLOT3_JTAG_TMS: J3.A8 R259.2(B)
SLOT3_JTAG_TRST_N: J3.B9 R252.2(B)
STRAP_I2C_SMBUS_CFG_EN_N: R113.2(B) R114.1 U1.Y3
STRAP_I2C_SMBUS_EN: R111.2(B) R112.1 U1.F4
STRAP_PLL_BYPASS_N: R117.2(B) U1.V17
STRAP_RESERVED0: R70.2(B) U1.V18
STRAP_RESERVED5: R59.1 U1.AD9
STRAP_RESERVED7: R61.1 U1.K3
STRAP_RESERVED9: R65.1 U1.B18
STRAP_RESERVED14: R69.2(B) U1.AD12
STRAP_RESERVED15: R64.2(B) U1.W14
STRAP_RESERVED16: R67.1 U1.V14
STRAP_RESERVED19: R60.2(B) U1.B12
STRAP_RESERVED20: R318.1 U1.AD6
STRAP_RESERVED21: R71.1 U1.AD3
STRAP_STN1_PORTCFG0: R62.2(B) R63.1 U1.H10
STRAP_STN2_PORTCFG0: R57.2(B) R58.1 U1.N19
STRAP_TESTMODE0: R115.2(B) R116.1 U1.V13
STRAP_UP_PORTSEL0: R68.1 U1.H18
STRAP_UP_PORTSEL1: R66.1 U1.M18
THER_SEN1_DN_1: C468.2(B) Q5.2(E) U10.3
THER_SEN1_DN_2: C469.2(B) Q6.2(E) U10.5
THER_SEN1_DP_1: C468.1 Q5.1 Q5.3 U10.2
THER_SEN1_DP_2: C469.1 Q6.1 Q6.3 U10.4
THER_SEN2_DN: C260.2(B) Q27.2(E) U4.3
THER_SEN2_DP: C260.1 Q27.1 Q27.3 U4.2
TLA2024_P0V9: C190.1 R148.2(B) U3.4
TLA2024_P1V8: C189.1 R146.2(B) U3.5
TLA2024_P3V3: C180.1 R147.2(B) U3.6
TP_A19: J5.A19
TP_A32: J5.A32
TP_A33: J5.A33
TP_A50: J5.A50
TP_B12: J5.B12
TP_B82: J5.B82
TP_PE_SLOT1_A19: J1.A19
TP_PE_SLOT1_A32: J1.A32
TP_PE_SLOT1_A33: J1.A33
TP_PE_SLOT1_A50: J1.A50
TP_PE_SLOT1_B82: J1.B82
UNNAMED_60_RES_I68_A: R135.1 U3.1
VR_P0V9_BT: PC587.1 PU23.14
VR_P0V9_PVIN: PC584.1 PC585.1 PC586.1 PC588.1 PC788.1 PC1588.1 PC1589.1 PL20.1 PR426.1 PU23.13
VR_P0V9_SW: PC587.2(B) PL11.1 PU23.12
VR_P1V8_BT: PC546.1 PU19.14
VR_P1V8_PVIN: PC543.1 PC545.1 PC548.1 PC550.1 PL9.1 PR370.1 PU19.12
VR_P1V8_SW: PC546.2(B) PL8.1 PU19.11
VR_P3V3_BT: PC514.1 PU17.14
VR_P3V3_PVIN: PC511.1 PC515.1 PC517.1 PC519.1 PC520.1 PC521.1 PL12.1 PR341.1 PU17.13
VR_P3V3_SW: PC514.2(B) PL6.1 PU17.12

Pads without a net: J2 A19 A32 A33 A50 B17 B31 B48 B82; J3 A19 A32 A33 A50 B17 B31 B48 B82; NOREF#4 1; NOREF#7 1; NOREF#20 1; NOREF#26 1; NOREF#41 1; NOREF#42 1; NOREF#45 1; NOREF#46 1; NOREF#47 1; NOREF#48 1; U3 2 7; U8 1; U11 1; U13 1; U16 1; U17 1; U19 1; U20 1; U47 1

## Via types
v1: diameter 0.762, hole 0.381, TOP to BOTTOM, 31 vias
v2: diameter 0.508, hole 0.254, TOP to BOTTOM, 2603 vias
v3: diameter 0.457, hole 0.254, TOP to BOTTOM, 407 vias
v4: diameter 0.635, hole 0.318, TOP to BOTTOM, 59 vias
v5: diameter 0.483, hole 0.254, TOP to BOTTOM, 10 vias
v6: diameter 0.406, hole 0.203, TOP to BOTTOM, 145 vias
v7: diameter 0.762, hole 0.254, TOP to BOTTOM, 10 vias

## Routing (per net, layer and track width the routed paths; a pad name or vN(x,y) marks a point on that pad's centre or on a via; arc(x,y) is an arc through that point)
GND: length 625.9
  TOP w0.178: v2(299.85,55.07) 299.85,55.37 300.11,55.63 U9.4 300.11,56.32
  TOP w0.203: v3(64.85,72.76) C10.2 ; C287.2 v3(61.65,71.96) C273.2 ; C53.2 v3(61.65,68.76) ; C6.2 v3(57.65,74.37) ; 64.54,80.18 v3(64.85,79.97) ; C136.2 v3(60.05,80.77) ; C269.2 v3(61.65,77.57) C283.2 ; C162.2 v3(58.45,79.97) C139.2 ; C277.2 v3(63.25,72.76) C290.2 ; v3(57.65,70.36) 57.89,70.6 C128.2 ; C16.2 v3(61.65,79.17) C22.2 ; C141.2 v3(67.25,75.16) ; C142.2 v3(64.85,69.56) ; C271.2 v3(61.65,73.56) C297.2 ; C133.2 v3(65.65,71.16) ; C164.2 v3(60.85,70.36) ; C134.2 v3(59.25,76.77) ; C17.2 v3(57.65,79.17) ; C2.2 v3(56.85,78.37) ; C281.2 v3(60.85,72.76) ; C294.2 v3(63.25,74.36) C418.2 ; C131.2 61.16,80.45 v3(61.65,79.97) C406.2 ; C19.2 v3(65.65,71.96) ; C398.2 v3(60.85,78.37) ; C146.2 v3(66.45,78.37) ; C18.2 v3(64.05,73.56) ; C135.2 v3(59.25,69.56) ; C426.2 v3(60.85,76.77) ; C148.2 v3(67.25,70.36) ; C4.2 v3(56.85,75.96) ; C442.2 v3(60.05,73.56) ; C410.2 v3(63.25,78.37) ; C150.2 v3(56.85,71.96) ; C20.2 v3(64.85,78.37) ; C21.2 v3(67.25,72.76) ; C14.2 v3(64.85,74.36) ; C422.2 v3(60.05,75.16) ; C394.2 v3(61.65,75.16) C430.2 ; C161.2 v3(68.05,79.17) ; v3(61.65,71.16) 61.78,71.04 C163.2 ; C132.2 v3(64.05,71.96) ; C144.2 v3(65.65,79.17) ; C279.2 v3(60.85,74.36) ; C151.2 v3(68.05,80.77) ; C402.2 v3(63.25,76.77) ; C9.2 v3(60.05,79.17) ; C137.2 v3(65.65,80.77) ; C7.2 v3(59.25,78.37) ; C390.2 v3(60.05,77.57) ; C438.2 v3(64.05,79.17) ; C434.2 v3(64.05,75.16) ; C414.2 v3(64.85,76.77) ; C15.2 v3(59.25,72.76) ; C130.2 v3(57.65,72.76) ; 59.46,81.25 v3(59.25,81.57) ; C275.2 v3(64.05,77.57)
  TOP w0.254: PC580.2 71.99,37.32 v2(72.37,37.7) ; v3(72.05,75.16) 73.66,75.16 R42.2 ; C143.2 66.63,77.1 v3(66.45,77.57) ; U3.3 262.72,30.63 R135.2 ; R133.2 59.25,84.77 v3(59.25,84.77) 59.29,84.73 R19.2 ; U12.4 118.97,41.87 v2(119.12,42.02) ; R23.2 72.74,79.93 v3(72.31,80.36) 72.74,80.79 R41.2 ; R24.2 72.74,78.45 v3(72.26,77.97) ; v2(160.99,115.44) 160.62,115.08 U13.3 ; R65.2 72.74,82.28 v3(72.26,82.77) 72.74,83.25 R134.2 ; v2(49.46,59.97) 49.18,59.69 47.72,59.69 PR505.2 ; v3(62.05,66.11) 61.92,66.25 R15.2 ; v3(65.65,67.96) 65.5,67.81 R61.2 ; v2(184.86,76.78) 184.86,76.99 184.35,77.5 U10.6 ; R18.2 72.87,73.41 72.56,73.1 72.48,73.1 ; 72.48,73.1 72.87,72.72 R38.2 72.87,72.32 R37.2 72.87,71.07 v3(72.47,70.67) 72.87,70.28 R17.2 ; 72.48,73.1 v3(72.26,73.1) ; R66.2 63.84,84.98 v3(64.05,84.77) 64.29,85 R20.2 ; v3(59.25,75.16) 58.96,75.46 C129.2 ; R68.2 67.19,83.9 v3(67.25,83.97) ; C54.2 v2(48.21,87.5) ; R58.2 61.69,83.2 v3(61.65,83.17) ; C181.2 v3(64.85,76.77) ; C386.2 v3(60.05,71.96) ; U8.3 v2(282.16,57.52) ; C194.2 v3(59.25,69.56) ; R16.2 72.87,68.66 v5(72.55,68.35) 72.28,68.07 R10.2 ; 65.17,77.78 v3(64.85,77.57)
  TOP w0.305: U2.12 v2(300.89,38.84)
  TOP w0.356: C49.2 v2(48.08,89.53) ; v2(283.03,66.62) 282.92,66.74 U16.3 ; U19.3 v2(281.55,85.08) ; C51.2 v2(48.08,88.52) ; U47.3 v2(276.03,28.14) ; C52.2 v2(48.46,95.89) ; v2(47.19,90.68) 47.77,90.68 C47.2 47.77,91.44 v2(47.19,91.44) ; U11.3 v2(280.13,27.68) ; C50.2 v2(47.32,95.89)
  TOP w0.381: C456.2 v2(280.89,31.01) ; R76.1 v2(304.5,63.96) ; C145.2 v2(71.45,62.99) ; C352.2 287.5,58.13 v2(287.45,58.09) 287.5,58.05 R310.2 ; C188.2 v2(45.16,92.02) ; C216.2 v2(295.1,59) ; R32.2 v2(27.89,106.81) R59.2 ; R31.2 v2(29.16,106.81) R12.2 ; R108.2 v2(66.37,62.87) ; R80.2 v2(306.96,31.98) ; C13.2 v2(45.16,88.9) ; v2(313.87,42.52) 313.89,42.55 R284.2 ; J5.A4 292.83,5.83 292.27,6.38 v2(292.27,7.04) ; v2(301.96,52.27) 301.81,52.42 C226.2 ; v2(262.95,31.64) R135.2 ; v3(64.45,66.11) 63.91,66.11 63.49,65.7 R36.2 ; R260.1 v2(292.56,70.21) ; R67.2 v2(55.96,93.34) R14.2 ; C191.2 v2(157.67,112.01) ; C221.2 v2(295.1,61.03) ; v2(43.12,103.59) 42.95,103.41 PC542.2 ; R75.2 65.56,67.06 R61.2 ; PC592.2 v2(49.1,36.8) ; C219.2 v2(297.77,63.52) ; PC1595.2 v2(53.14,63.98) ; v2(64.71,37.52) PC584.2 ; C184.2 v2(45.16,87.88) ; R282.2 v2(315.16,42.52) ; C243.2 v2(294.59,70.23) ; R114.2 R71.2 v2(22.81,106.93) ; v2(56.85,62.89) R73.2 ; C227.2 v2(301.09,53.67) ; R318.2 v2(25.86,108.97) ; R13.2 v2(54.81,93.34) R132.2 ; C220.2 v2(295.1,56.97) ; C178.2 v2(263.48,24.49) ; C160.2 v2(71.2,90.17) ; C1.2 v2(63.98,101.49) ; C190.2 v2(258.47,28.91) ; R33.2 v2(34.88,106.19) ; C127.2 v2(52.66,93.34) ; C223.2 v2(309.12,37.69) ; C147.2 v2(72.47,62.99) ; C12.2 v2(75.01,90.3) ; v2(297.38,69.95) 296.59,69.95 C242.2 296.53,70.59 v2(297.36,70.59) ; R84.2 v2(309.96,42.42) ; C157.2 v2(288.37,29.41) ; C244.2 v2(293.57,70.23) ; R200.2 v2(289.62,43.45) ; R2.2 v2(298.53,52.27) ; v2(282.4,28.32) 282.92,27.8 U17.3 ; C8.2 v2(72.59,90.17) ; v5(73.99,73.15) 74.25,73.41 R63.2 ; R112.2 v2(67.39,62.87) ; PC543.2 v2(48.62,110.87) ; C176.2 v2(48.08,36.83) ; PC553.2 v2(43.64,114.43) ; C11.2 v2(45.16,89.92) ; C452.2 v2(315.91,32.87) ; C257.2 v2(305.54,62.04) ; R35.2 v2(26.87,108.97) ; PC551.2 v2(56.59,109.98) ; C149.2 v2(45.16,91.01) ; R43.2 31.19,108.46 v2(31.7,108.97) 32.21,108.46 R11.2 ; C174.2 v2(46.41,37.45) ; R199.2 v2(288.88,84.84) ; R82.2 v2(308.81,42.42) ; U20.3 v2(283.53,44.56) ; C156.2 v2(287.35,29.41) ; C455.2 v2(280.87,71.65) ; R294.2 v2(313.89,34.42) ; R116.2 v2(53.67,91.31) ; C180.2 v2(261.44,24.43) ; C179.2 v2(264.49,24.51) ; C159.2 v2(278.1,24.49) ; R286.2 v2(312.62,42.52) ; C177.2 v2(45.16,86.87) ; v2(258.52,27.89) C189.2
  TOP w0.457: PC541.2 47.87,102.7 v2(48.21,102.36) ; C3.2 v2(66.37,90.35) ; C460.2 v2(286.52,85.58) ; v2(70.44,96.01) 70.44,95.44 C48.2 71.45,95.44 v2(71.45,96.01) ; PC581.1 65.48,47.73 v2(64.76,47.73) ; C218.2 v2(300.68,64.14) ; C215.2 v2(306.94,55.32) ; C461.2 v2(286.51,45.07) ; C224.2 v2(296.25,53.54) ; U6.4 68.15,94.56 v2(67.67,95.05) ; C258.2 v2(306.15,59.13) ; C172.2 v2(278.84,31.65) ; C225.2 v2(298.26,54.67) ; C217.2 v2(305.97,56.59) ; C158.2 v2(286.84,44.12) ; C222.2 v2(303.22,63.96) ; v2(70.7,47.57) PC583.2
  TOP w0.508: C465.2 19.38,98.68 v2(19.66,98.4) ; J5.A63 231.83,6.54 v2(231.33,7.04) ; v2(270.34,7.04) 270.83,6.55 J5.A24 ; v2(256.32,7.04) 256.83,6.53 J5.A38 ; Q3.S v2(295.42,48.8) ; R358.1 292.56,12.06 292.83,12.33 J1.A4 ; C253.2 C254.2 v2(283.54,11.81) ; v2(217.31,7.04) 216.83,6.55 J5.A78 ; J5.A54 240.83,6.53 v2(241.34,7.04) ; J5.A46 248.83,6.53 v2(248.32,7.04) ; v2(277.33,7.04) 277.33,6.49 276.83,5.99 J5.A18 ; PR340.2 300.34,103.27 v2(300.36,103.25) ; J5.A67 227.83,6.55 v2(227.34,7.04) ; J5.A37 257.83,6.53 v2(258.33,7.04) ; J5.A66 228.83,6.54 v2(229.33,7.04) ; C252.2 287.99,23.75 v2(288.62,24.38) ; v2(272.33,7.04) 271.83,6.54 J5.A23 ; Q1.S 169.9,111.89 v2(168.86,111.89) ; v2(168.86,115.32) 169.9,115.32 Q2.S ; J5.A74 220.83,6.54 v2(221.33,7.04) ; v2(225.34,7.04) 224.83,6.53 J5.A70 ; v2(299.8,48.46) 300.52,47.74 Q4.S ; J5.A49 245.83,5.97 246.32,6.47 v2(246.32,7.04) ; J5.A59 235.83,6.53 v2(235.31,7.04) ; J5.A58 236.83,6.54 v2(237.33,7.04) ; C248.2 v2(286.84,84.71) ; v2(233.32,7.04) 232.83,6.55 J5.A62 ; v2(306.91,22.35) 306.57,22.01 Q7.S ; v2(243.34,7.04) 243.83,6.55 J5.A51 ; C467.2 v2(15.83,86.36) ; J5.A28 266.83,6.54 v2(266.33,7.04) ; J5.A71 223.83,6.54 v2(223.33,7.04) ; C251.2 C250.2 296.64,11.93 v2(297.21,12.5) ; v2(274.33,7.04) 274.83,6.54 J5.A20 ; J5.A42 252.83,6.55 v2(252.33,7.04) ; J5.A75 219.83,6.53 v2(219.31,7.04) ; v2(254.32,7.04) 253.83,6.55 J5.A41 ; J5.A27 267.83,6.53 v2(268.34,7.04) ; J5.A15 279.83,6.55 v2(279.33,7.04) ; J5.A31 263.83,6.07 264.33,6.57 v2(264.33,7.04) ; v2(215.6,7.04) 215.83,6.82 J5.A79 ; v2(250.33,7.04) 249.83,6.53 J5.A45 ; v2(239.33,7.04) 239.83,6.54 J5.A55 ; U7.4 v2(311.35,42.55) ; v2(260.33,7.04) 260.83,6.55 J5.A34
  TOP w0.635: C193.2 v2(162.89,111.38)
  TOP w0.762: C192.2 v2(161.37,111.63) ; CON1.4 v2(188.67,109.78)
  IN1 w0.254: v3(63.25,72.76) 62.64,72.15 62.64,67.69 59.21,64.26 54.05,64.26 53.67,64.64 49.73,64.64 48.59,63.5 48.59,61.47 v2(48.72,61.34)
  BOTTOM w0.254: U1.AA3 55.65,68.36 v3(55.25,67.96) 54.85,68.36 U1.AB3 ; U1.N4 v3(61.65,68.76) U1.P3 61.07,68.18 60.64,68.18 60.46,68.37 U1.R3 ; U1.N10 v3(61.65,73.56) ; U1.L21 63.65,82.77 v3(64.05,83.17) 64.45,82.77 U1.K21 ; v2(48.72,61.34) 48.59,61.21 48.59,60.04 48.06,59.51 47.54,59.51 PR505.2 ; U1.F12 v3(68.05,75.16) U1.E12 ; v3(60.85,74.36) U1.P11 ; U1.P13 v3(60.85,76.77) ; U1.T23 v3(59.25,84.77) ; U1.D9 v3(68.85,72.76) U1.E9 ; U1.Y12 v3(56.85,75.96) U1.W12 ; U1.AC21 53.85,82.56 53.85,82.18 54.05,81.98 U1.AC20 ; U1.L3 63.65,68.36 v3(63.25,67.96) 62.85,68.36 U1.M3 ; U1.C21 70.05,82.77 v3(69.65,83.17) ; U1.W4 v3(56.85,68.76) ; U1.C14 70.06,77.16 v3(70.45,76.77) U1.C13 ; U1.N5 v3(61.65,69.56) ; PC506.2 300.7,111.74 PR333.2 300.97,110.49 v2(301.86,110.49) ; U1.AC19 54.05,81.16 v3(53.65,80.77) ; v2(311.1,80.26) 310.55,79.72 U4.5 ; U1.R16 v3(60.05,79.17) ; U1.N1 62.05,66.12 v3(62.05,66.11) ; U1.G3 66.86,68.37 v3(67.25,68.76) U1.G4 ; v3(61.65,79.17) 62.05,78.77 U1.N16 ; U1.P9 v3(60.85,72.76) ; U1.AB6 v3(55.25,70.36) U1.AA6 ; U1.C8 69.9,72.52 69.9,73.01 U1.C9 v3(70.45,73.57) 70.05,73.97 U1.C10 ; U1.C7 70.06,71.57 v3(70.45,71.17) ; v3(60.05,77.57) 60.45,77.17 U1.R14 ; U1.T15 v3(59.25,78.37) ; v3(68.85,83.17) 69.25,82.77 U1.D21 ; U1.J3 65.25,68.36 v3(65.65,67.96) 66.05,68.36 U1.H3 ; v3(52.05,67.96) 52.45,68.36 U1.AE3 ; U1.T9 v3(59.25,72.76) ; v5(72.55,68.35) 72.53,68.37 U1.A3 ; U1.P15 v3(60.85,78.37) ; U1.Y7 v3(56.05,71.16) ; U1.D18 v3(69.65,80.77) U1.C18 ; U1.K23 v3(64.05,84.77) ; U1.Y8 56.45,72.36 v3(56.05,71.96) ; U1.AC4 53.85,68.96 53.85,68.57 U1.AC3 ; U1.T1 59.65,66.12 v3(59.65,66.11) ; U1.E18 v3(68.85,80.77) ; U1.E15 v3(68.85,78.37) ; U1.F15 v3(68.05,78.37) ; U1.Y1 v3(56.85,66.36) U1.W1 ; U1.A6 72.38,70.76 v3(72.47,70.67) ; U1.G23 66.86,84.37 v3(67.25,83.97) U1.G22 ; U1.F9 v3(68.05,72.76) ; v3(72.26,73.1) 72.2,73.16 U1.A9 ; U1.J21 v3(64.85,82.37) U1.K20 ; U1.G5 66.85,69.96 v3(67.25,69.56) ; U1.C22 v3(70.45,83.97) 70.06,84.37 U1.C23 ; U1.T4 v3(59.25,68.76) ; U1.R10 v3(60.05,73.56) ; U1.L8 v3(64.05,71.96) ; U1.K13 v3(64.85,76.77) ; U1.D12 v3(69.65,75.16) U1.C12 ; U1.K4 64.46,69.16 v3(64.85,69.56) U1.K5 ; U1.M15 v3(63.25,78.37) U1.L16 v3(64.05,79.17) ; v3(72.26,82.77) 72.26,82.76 U1.A21 ; U1.V3 58.05,68.36 v3(58.45,67.96) U1.U3 ; U1.AE6 v3(52.05,70.36) ; v3(52.05,77.56) 52.45,77.96 U1.AE15 ; U1.C20 70.06,81.97 v3(70.45,81.57) U1.C19 ; U1.M13 v3(63.25,76.77) ; U1.R12 v3(60.05,75.16) ; U1.AA9 v3(56.05,72.76) U1.Y9 ; U1.AE18 52.45,80.36 v3(52.05,79.96) ; U1.R8 v3(60.05,71.96) ; U1.N8 62.05,72.36 v3(61.65,71.96) ; U1.F18 v3(68.05,80.77) ; U1.N20 v3(61.65,82.37) ; U1.AD15 v3(52.85,77.57) ; U1.A18 72.31,80.37 v3(72.31,80.36) ; U1.A15 v3(72.26,77.97) ; U1.K11 v3(64.85,74.36) ; U1.L14 v3(64.05,77.57) U1.K15 ; U1.C15 v3(70.45,78.37) ; U1.G1 v3(67.25,66.36) ; v3(70.18,65.72) 70.29,65.82 70.29,66.57 70.09,66.76 U1.C1 ; U1.AC6 53.93,70.89 53.93,71.44 U1.AC7 ; U1.N12 v3(61.65,75.16) ; U1.H21 66.05,82.77 v3(65.65,83.17) ; v3(68.05,83.17) 68.45,82.77 U1.E21 ; U1.AC16 v3(54.45,78.37) U1.AC15 ; U1.A12 v3(72.05,75.16) ; U1.T11 v3(59.25,74.36) ; U1.G2 v3(67.25,67.16) ; U1.D15 v3(69.65,78.37) ; U1.C16 v3(70.45,79.17) 70.06,79.56 U1.C17 ; U1.L12 v3(64.05,75.16) ; PC539.2 44.02,109.66 ; U1.V6 v3(57.65,70.36) ; U1.AC9 53.95,73.27 53.95,73.86 U1.AC10 ; U1.L10 v3(64.05,73.56) ; U1.K1 64.45,66.12 v3(64.45,66.11) ; U1.W9 v3(56.85,72.76) ; U1.N14 62.05,77.17 v3(61.65,77.57) ; U1.T13 v3(59.25,76.77) ; U1.K9 v3(64.85,72.76) ; U1.C11 v3(70.45,75.16) ; U1.G18 v3(67.25,80.77) ; U1.V9 v3(57.65,72.76) ; U1.AE9 v3(52.05,72.76) ; U1.G15 v3(66.45,78.37) ; U1.AE21 v3(52.05,82.36)
  BOTTOM w0.279: U1.M9 v3(63.25,72.76) ; U1.G21 66.86,82.76 v3(67.25,82.37) U1.G20 ; U1.G12 v3(67.25,75.16) ; U1.M11 v3(63.25,74.36) ; U1.G19 v3(67.25,81.57)
  BOTTOM w0.305: U1.AB21 v3(54.45,83.17)
  BOTTOM w0.356: PR361.2 v2(41.61,105.08) ; v2(11.69,72.74) 11.7,72.73 J8.13 ; U1.G6 v3(67.25,70.36) ; U1.G9 v3(67.25,72.76)
  BOTTOM w0.381: v2(11.58,38.3) 11.61,38.28 J7.1 ; U1.AC2 v3(54.45,67.96) 54.05,68.36 U1.AC3 ; v3(70.45,68.77) 70.06,69.16 U1.C4 ; v2(11.69,70.9) 11.71,70.93 J8.10 ; U1.W22 v3(56.85,83.17) U1.Y21 ; U1.AA12 U1.AB12 v3(54.45,75.16) ; U1.U21 v3(58.45,83.17) 58.05,82.77 U1.V21 ; U1.W18 v3(56.85,79.97) 57.25,79.57 U1.W17 ; J8.32 17.09,76.33 v2(17.1,76.32) ; J8.35 17.08,74.53 v2(17.1,74.54) ; U1.F6 v3(68.05,70.36) ; U1.C5 v3(69.65,70.36) ; v3(69.65,70.36) U1.D6 ; v3(69.65,70.36) U1.C6 ; J7.26 16.86,52.68 v2(17.1,52.91) ; J7.32 v2(17.32,49.08) ; v2(11.69,78.09) 11.72,78.13 J8.22 ; J8.25 v2(11.72,79.93) ; J7.19 11.7,49.08 v2(11.69,49.09) ; U1.AC18 v3(54.45,80.77) U1.AB18 ; v3(54.45,75.16) U1.AC11 ; v3(54.45,75.16) U1.AC12 ; U1.P21 61.25,82.77 v3(60.85,83.17) U1.R21 ; J8.16 11.73,74.53 v2(11.69,74.49) ; v3(53.62,65.47) 53.62,66.33 U1.AC1 ; J8.7 11.72,69.13 v2(11.69,69.16) ; C259.2 v2(306.66,75.55) ; v2(17.45,43.64) 17.42,43.68 J7.41 ; PR369.2 41.99,104.58 41.61,104.96 v2(41.61,105.08) ; U1.W23 57.25,84.36 v3(56.85,83.97) U1.Y23 ; v2(17.27,65.57) 17.23,65.53 J8.50 ; J8.4 11.71,67.33 v2(11.69,67.3) ; J8.1 11.71,65.53 v2(11.69,65.55) ; U1.E6 v3(68.85,70.36) ; J7.13 11.67,45.48 v2(11.66,45.48) ; C451.2 v2(121.79,41.04) ; U1.AC23 v3(53.65,84.77) ; U1.AC9 54.45,72.77 v3(54.45,72.76) U1.AC8 ; v2(177.73,80.14) 178.14,80.55 C265.2 ; J5.B7 289.83,5.78 290.17,6.12 290.17,6.98 v2(290.27,7.08) ; U1.C3 70.05,68.36 v3(69.65,67.96) U1.C2 ; v2(11.58,40.04) 11.62,40.08 J7.4 ; U1.AB9 v3(55.25,72.76) ; U1.W19 57.25,81.17 v3(56.85,81.57) ; J8.26 16.95,79.93 v2(17.18,80.15) ; J8.19 11.71,76.33 v2(11.69,76.35) ; v2(17.1,72.64) 17.01,72.73 J8.38 ; J7.29 v2(17.22,50.87) ; U1.AC13 v3(53.65,76.77) U1.AC14 ; C450.2 v2(121.81,36.72) ; v2(11.61,41.9) 11.64,41.87 J7.7 ; U1.W20 v3(56.85,82.37) 57.25,82.76 U1.W21 ; J8.29 17.16,78.13 v2(17.17,78.14) ; U1.AC22 v3(53.65,83.17) 54.05,82.77 U1.AC21 ; v3(56.05,79.96) 56.45,80.36 U1.Y18 ; v2(17.1,70.73) 16.9,70.93 J8.41 ; U1.T5 v3(59.25,69.56) ; v2(11.66,47.23) 11.71,47.27 J7.16 ; J7.35 17.02,47.27 v2(17.22,47.07) ; v2(17.1,68.98) 16.95,69.13 J8.44 ; v2(291.78,108.08) PC511.2 ; U1.AC5 v3(54.45,70.36) 54.45,70.37 U1.AC6 ; U1.Y15 v3(56.05,78.37) U1.AA15 ; J8.47 17.26,67.33 v2(17.27,67.31) ; J7.47 17.3,40.08 17.48,39.89 v2(17.48,39.85) ; v3(61.65,83.17) 62.05,82.77 U1.N21 U1.M21 ; J7.44 v2(17.36,41.87) ; v2(11.69,50.84) 11.72,50.87 J7.22 ; U1.D3 69.25,68.36 v3(68.85,67.96) U1.E3 ; v2(17.35,45.67) 17.15,45.48 J7.38 ; U1.AB15 v3(55.25,78.37) ; J7.10 11.64,43.68 v2(11.61,43.65) ; U1.AC17 54.05,79.57 v3(53.65,79.97) ; U1.T20 v3(59.25,82.37) ; J7.25 v2(11.65,52.68) ; U1.N23 v3(61.65,84.77) ; J7.50 v2(17.19,38.28) ; C177.2 v2(45.16,86.87) ; U1.AE12 v2(51.8,75.56)
  BOTTOM w0.457: PC508.1 v2(295.56,99.44) ; v2(299.8,99.87) PC510.2
  BOTTOM w0.508: v2(229.33,7.04) 229.83,6.54 J5.B65 ; J5.B53 241.83,6.55 v2(241.34,7.04) ; J5.B35 259.83,6.53 v2(260.33,7.04) ; v2(225.34,7.04) 225.83,6.55 J5.B69 ; v2(279.33,7.04) 278.83,6.53 J5.B16 ; v2(233.32,7.04) 233.83,6.53 J5.B61 ; v2(268.34,7.04) 268.83,6.55 J5.B26 ; v2(250.33,7.04) 250.83,6.55 J5.B44 ; v2(237.33,7.04) 237.83,6.54 J5.B57 ; v2(272.33,7.04) 272.83,6.54 J5.B22 ; v2(258.33,7.04) 258.83,6.55 J5.B36 ; J5.B29 265.83,6.54 v2(266.33,7.04) ; J5.B73 221.83,6.54 v2(221.33,7.04) ; v2(270.34,7.04) 269.83,6.53 J5.B25 ; J5.B43 251.83,6.53 v2(252.33,7.04) ; v2(248.32,7.04) 247.83,6.55 J5.B47 ; v2(239.33,7.04) 238.83,6.54 J5.B56 ; v2(235.31,7.04) 234.83,6.55 J5.B60 ; v2(292.27,7.04) 292.27,6.48 292.83,5.93 J5.A4 ; v2(256.32,7.04) 255.83,6.55 J5.B39 ; J5.B80 214.83,6.26 v2(215.6,7.04) ; J5.B13 281.83,7 v2(281.87,7.04) ; v2(227.34,7.04) 226.83,6.53 J5.B68 ; J5.B40 254.83,6.53 v2(254.32,7.04) ; J5.A49 245.83,5.94 245.31,6.46 v2(245.31,7.04) ; v2(274.33,7.04) 273.83,6.54 J5.B21 ; J5.A18 276.83,5.95 276.3,6.48 v2(276.3,7.04) ; v2(262.53,7.04) 262.83,6.74 J5.B32 ; J5.B77 217.83,6.53 v2(217.31,7.04) ; J5.B72 222.83,6.54 v2(223.33,7.04) ; J5.B52 242.83,6.53 v2(243.34,7.04) ; J5.B76 218.83,6.55 v2(219.31,7.04) ; v5(71.88,44.98) 71.72,44.82 PR424.2 ; J5.B64 230.83,6.54 v2(231.33,7.04)
  vias: v1(287.13,105.51) v2(0.76,104.98) v2(0.76,99.9) v2(0.76,94.82) v2(0.76,89.74) v2(0.76,84.66) v2(3.58,33.17) v2(8.66,33.17) v2(9.93,79.9) v2(9.93,78.15) v2(9.93,76.31) v2(9.93,74.57) v2(9.96,72.71) v2(9.96,70.96) v2(9.98,69.1) v2(9.98,67.35) v2(9.96,52.67) v2(9.96,50.92) v2(9.96,49.06) v2(9.96,47.31) v2(9.98,45.45) v2(9.98,43.71) v2(9.96,41.85) v2(9.96,40.1) v2(11.38,117.48) v2(13.03,102.87) v2(13.03,102.23) v2(13.03,97.41) v2(13.03,96.65) v2(13.08,90.88) v2(13.08,90.12) v2(13.74,33.17) v2(16.46,117.48) v2(18.82,33.17) v2(21.54,117.48) v2(23.9,33.17) v2(25.6,95.89) v2(25.6,94.87) v2(26.37,95.89) v2(26.37,94.87) v2(26.62,117.48) v2(27.13,95.89) v2(27.13,94.87) v2(27.89,95.89) v2(27.89,94.87) v2(28.98,33.17) v2(31.7,117.48) v2(34.62,85.6) v2(35.76,88.39) v2(35.76,87.5) v2(35.76,86.61) v2(36.78,117.48) v2(41.86,117.48) v2(42.95,33.17) v2(43.31,108.51) v2(45.26,110.27) v2(45.26,109.38) v2(46.05,57.91) v2(46.05,57.28) v2(46.05,56.64) v2(46.94,117.48) v2(47.17,103.64) v2(47.8,104.35) v2(47.8,103.66) v2(48.03,33.17) v2(48.38,104.63) v2(48.41,103.97) v2(49.48,59.18) v2(49.53,58.32) v2(49.53,57.3) v2(49.53,56.29) v2(50.88,58.55) v2(50.88,57.86) v2(51.72,60.05) v2(51.69,59.08) v2(52.02,117.48) v2(52.4,110.49) v2(52.4,109.86) v2(52.4,109.22) v2(53.11,33.17) v2(53.85,59.94) v2(53.85,59.03) v2(54.51,58.24) v2(55.04,58.67) v2(55.07,57.89) v2(55.75,58.06) v2(55.75,57.23) v2(56.16,58.93) v2(56.32,35.47) v2(56.98,35.47) v2(57.1,117.48) v2(58.02,109.47) v2(58.19,33.17) v2(58.4,110.11) v2(58.78,109.47) v2(59.16,110.11) v2(59.54,109.47) v2(60.43,102.92) v2(60.43,102.23) v2(61.06,102.92) v2(61.06,102.23) v2(61.48,40.12) v2(61.47,39.32) v2(61.65,47.96) v2(61.85,47.04) v2(62.18,117.48) v2(62.41,46.47) v2(62.65,48.25) v2(62.67,47.52) v2(63.03,46.9) v2(63.34,46.32) v2(63.27,33.17) v2(63.36,48.2) v2(63.36,47.49) v2(63.46,45.58) v2(63.79,46.83) v2(64.12,47.41) v2(64.09,46.23) v2(64.4,36.16) v2(64.4,35.5) v2(64.5,46.75) v2(64.88,46.19) v2(65.26,46.78) v2(65.65,46.22) v2(67.26,117.48) v2(68.03,39.11) v2(68.01,38.45) v2(68.01,37.46) v2(68.01,36.77) v2(68.02,35.97) v2(68.35,33.17) v2(72.34,117.48) v2(73.43,33.17) v2(77.42,117.48) v2(78.51,33.17) v2(82.5,117.48) v2(83.59,33.17) v2(87.58,117.48) v2(88.67,33.17) v2(92.66,117.48) v2(93.75,33.17) v2(97.74,117.48) v2(98.83,33.17) v2(102.82,117.48) v2(103.91,33.17) v2(107.9,117.48) v2(108.99,33.17) v2(112.98,117.48) v2(114.07,33.17) v2(118.06,117.48) v2(119.15,33.17) v2(123.14,117.48) v2(124.23,33.17) v2(128.22,117.48) v2(129.31,33.17) v2(133.3,117.48) v2(138.38,117.48) v2(143.28,33.17) v2(143.46,117.48) v2(148.36,33.17) v2(148.54,117.48) v2(153.44,33.17) v2(153.62,117.48) v2(158.52,33.17) v2(158.7,117.48) v2(163.6,33.17) v2(163.78,117.48) v2(168.86,117.48) v2(169.1,32.25) v2(169.81,26.85) v2(169.81,16) v2(173.36,14.67) v2(173.94,117.48) v2(178.44,14.67) v2(179.02,117.48) v2(183.52,14.67) v2(184.1,117.48) v2(188.6,14.67) v2(189.18,117.48) v2(193.68,14.67) v2(194.26,117.48) v2(199.19,13.93) v2(199.34,117.48) v2(204.42,117.48) v2(204.49,12.19) v2(209.5,117.48) v2(209.95,11.18) v2(213.6,7.04) v2(214.58,117.48) v2(219.66,117.48) v2(224.74,117.48) v2(229.82,117.48) v2(234.9,117.48) v2(239.98,117.48) v2(245.06,117.48) v2(250.14,117.48) v2(255.22,117.48) v2(260.3,117.48) v2(265.38,117.48) v2(267.54,29.72) v2(270.46,117.48) v2(274.66,111.71) v2(274.66,109.55) v2(274.66,107.39) v2(274.66,105.23) v2(274.66,103.07) v2(274.66,100.91) v2(274.66,98.76) v2(274.92,31.06) v2(275.42,111.71) v2(275.42,109.55) v2(275.42,107.39) v2(275.42,105.23) v2(275.42,103.07) v2(275.42,100.91) v2(275.42,98.76) v2(275.54,117.48) v2(276.67,31.06) v2(279.71,24.26) v2(280.24,9.14) v2(280.32,113.07) v2(280.62,117.48) v2(281.03,113.07) v2(281.8,112.78) v2(281.81,108.95) v2(281.81,108.29) v2(281.86,110.36) v2(281.86,109.71) v2(282.4,10.16) v2(283.01,8.56) v2(284.15,69.34) v2(284.43,28.57) v2(285.07,69.34) v2(285.14,24.69) v2(285.14,23.88) v2(285.7,117.48) v2(286.08,29.08) v2(286.06,7.06) v2(286.21,69.72) v2(287.48,70.23) v2(288.49,70.23) v2(289.21,68.45) v2(289.51,113.28) v2(290.78,117.48) v2(290.84,101.48) v2(290.91,113.03) v2(291.06,28.83) v2(291.22,100.95) v2(291.54,83.95) v2(291.54,83.19) v2(291.54,43.31) v2(291.54,42.55) v2(291.57,101.48) v2(291.8,102.08) v2(291.92,113.03) v2(291.95,100.95) v2(292.11,102.66) v2(292.26,101.53) v2(292.43,29.59) v2(292.61,102.09) v2(292.64,101) v2(292.74,102.82) v2(293.02,101.53) v2(293.07,113.03) v2(293.22,68.33) v2(293.38,102.07) v2(293.43,100.94) v2(293.45,29.59) v2(293.57,102.74) v2(293.78,101.56) v2(293.78,21.44) v2(294.08,113.03) v2(294.27,101.12) v2(294.46,101.85) v2(294.46,29.59) v2(294.87,26.52) v2(295.23,113.03) v2(295.86,117.48) v2(295.89,7.98) v2(296.24,113.03) v2(297.38,113.03) v2(298.27,113.03) v2(298.42,66.09) v2(299.29,60.15) v2(299.29,58.75) v2(299.29,57.22) v2(299.26,44.63) v2(299.87,21.39) v2(300.16,66.09) v2(300.69,60.15) v2(300.71,58.7) v2(300.69,57.22) v2(300.81,9.17) v2(300.94,117.48) v2(300.86,44.68) v2(301.87,49.53) v2(302.09,60.15) v2(302.09,58.75) v2(302.09,57.22) v2(303.62,49.53) v2(304.24,19.3) v2(304.24,18.54) v2(304.24,17.27) v2(304.24,16.38) v2(304.67,44.17) v2(305.89,9.17) v2(306.02,117.48) v2(306.12,52.07) v2(307.27,41.58) v2(307.92,51.97) v2(309.15,26.8) v2(309.72,54.64) v2(309.66,51.97) v2(310.21,30.43) v2(310.97,9.17) v2(311.1,117.48) v2(311.47,54.64) v2(312.52,31.34) v2(312.93,77.22) v2(314.48,48.49) v2(314.58,79.38) v2(314.71,50.67) v2(314.89,30.02) v2(316.05,9.17) v2(316.18,117.48) v2(320.83,117.47) v2(321.29,112.17) v2(321.29,107.09) v2(321.29,102.01) v2(321.29,96.93) v2(321.29,91.85) v2(321.29,86.77) v2(321.29,81.69) v2(321.29,76.61) v2(321.29,71.53) v2(321.29,66.45) v2(321.29,61.37) v2(321.29,56.29) v2(321.29,51.21) v2(321.29,46.13) v2(321.29,41.05) v2(321.29,35.97) v2(321.29,30.89) v2(321.29,25.81) v2(321.29,20.73) v2(321.29,15.65) v2(321.29,10.57) v4(53.33,104.98) v4(56.67,58.04) v4(59.18,47.14) v4(66.53,35.95) v4(273.76,113.16) v4(289.49,114.76) v4(295.1,102.29) v4(301.35,59.54)
